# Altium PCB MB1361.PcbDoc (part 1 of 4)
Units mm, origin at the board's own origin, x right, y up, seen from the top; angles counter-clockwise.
Board outline 70 x 133.34 mm, 6 copper layers (Top Layer, Signal Layer 1, Signal Layer 2, Signal Layer 3, Signal Layer 4, Bottom Layer), stack 1.578 mm thick; 268 components, 251 nets, 1066 pads, 705 vias.
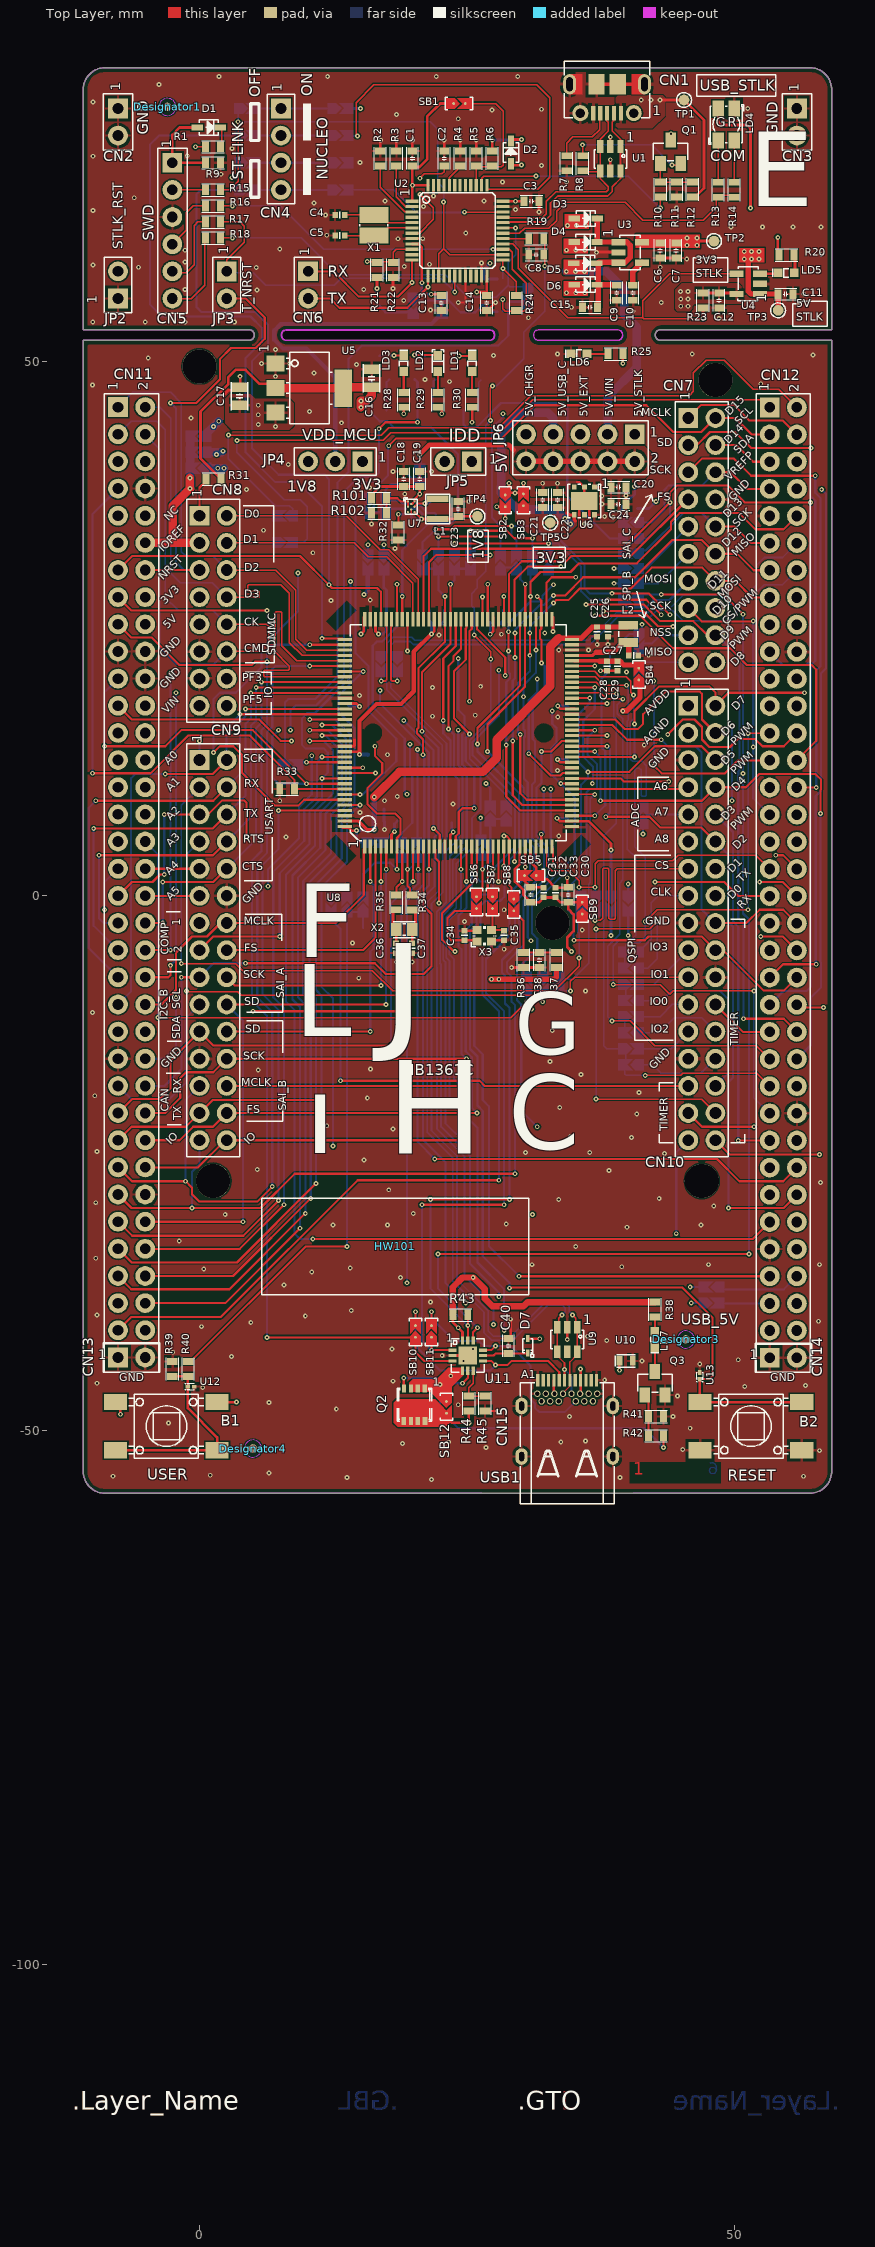
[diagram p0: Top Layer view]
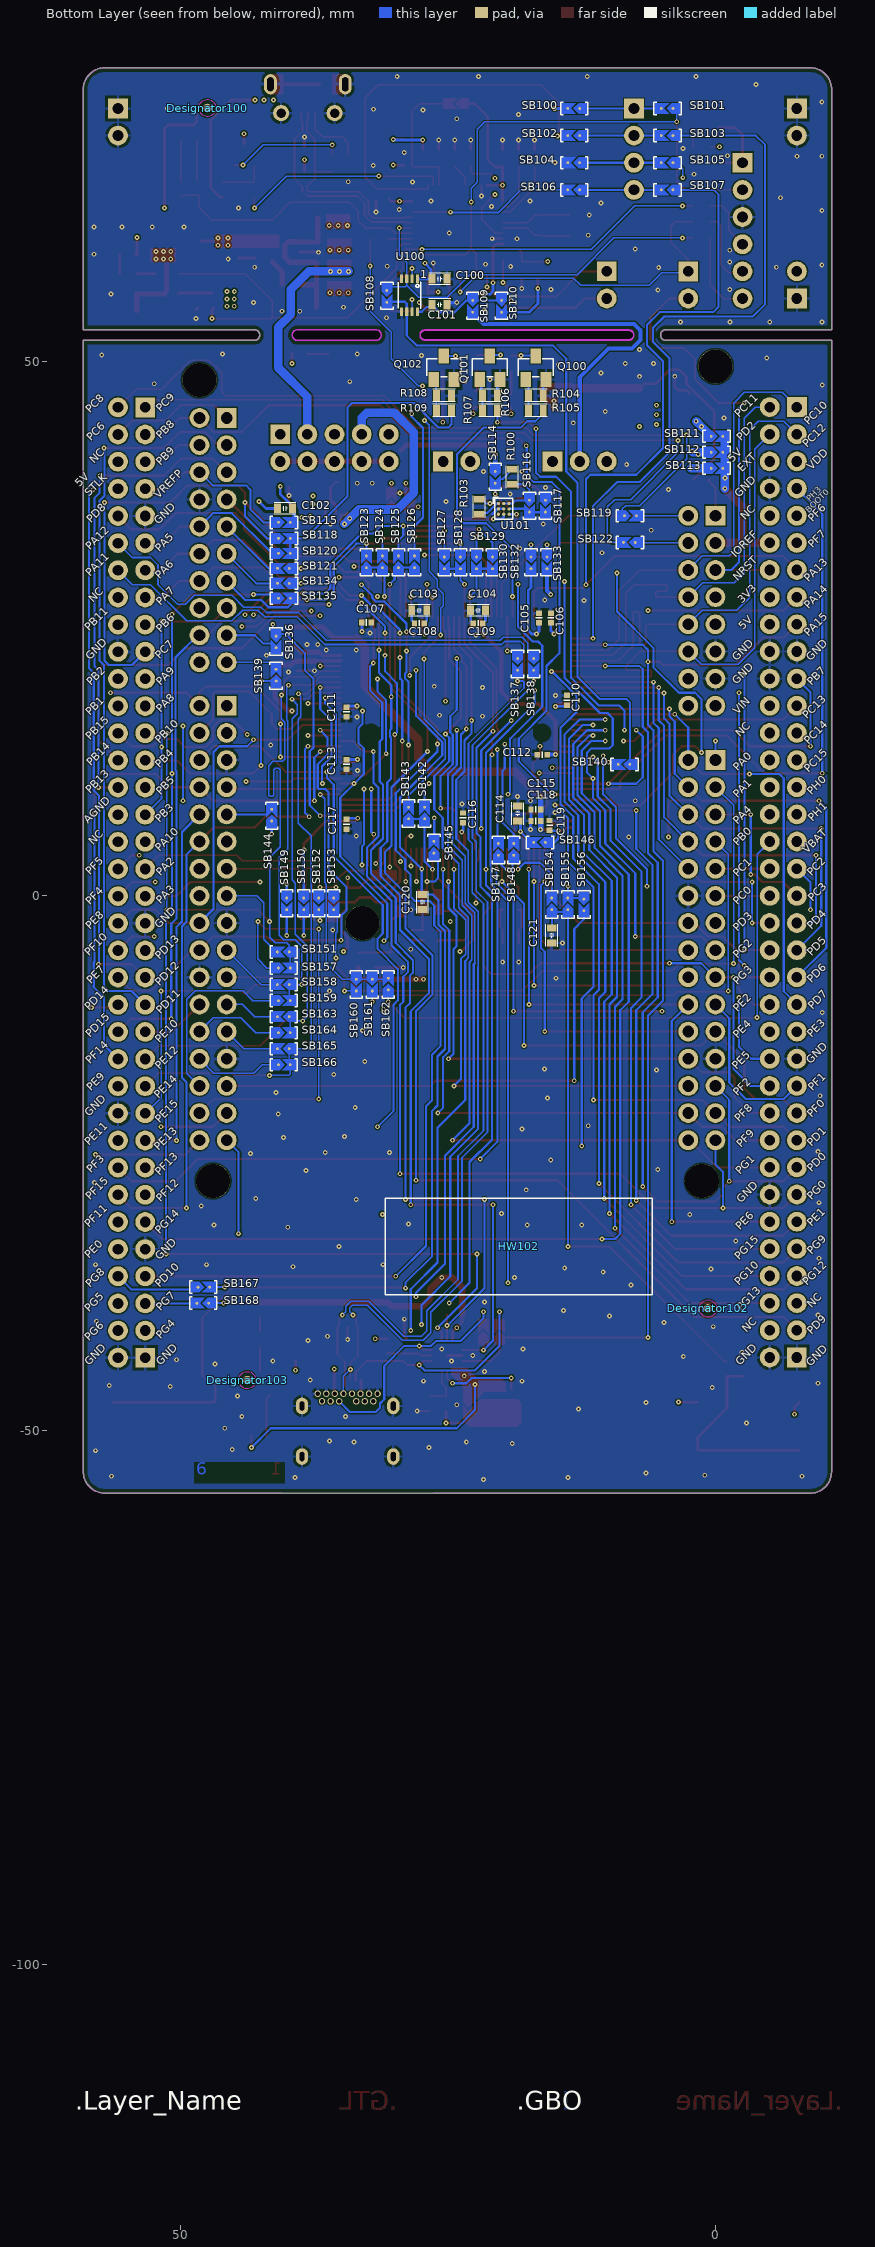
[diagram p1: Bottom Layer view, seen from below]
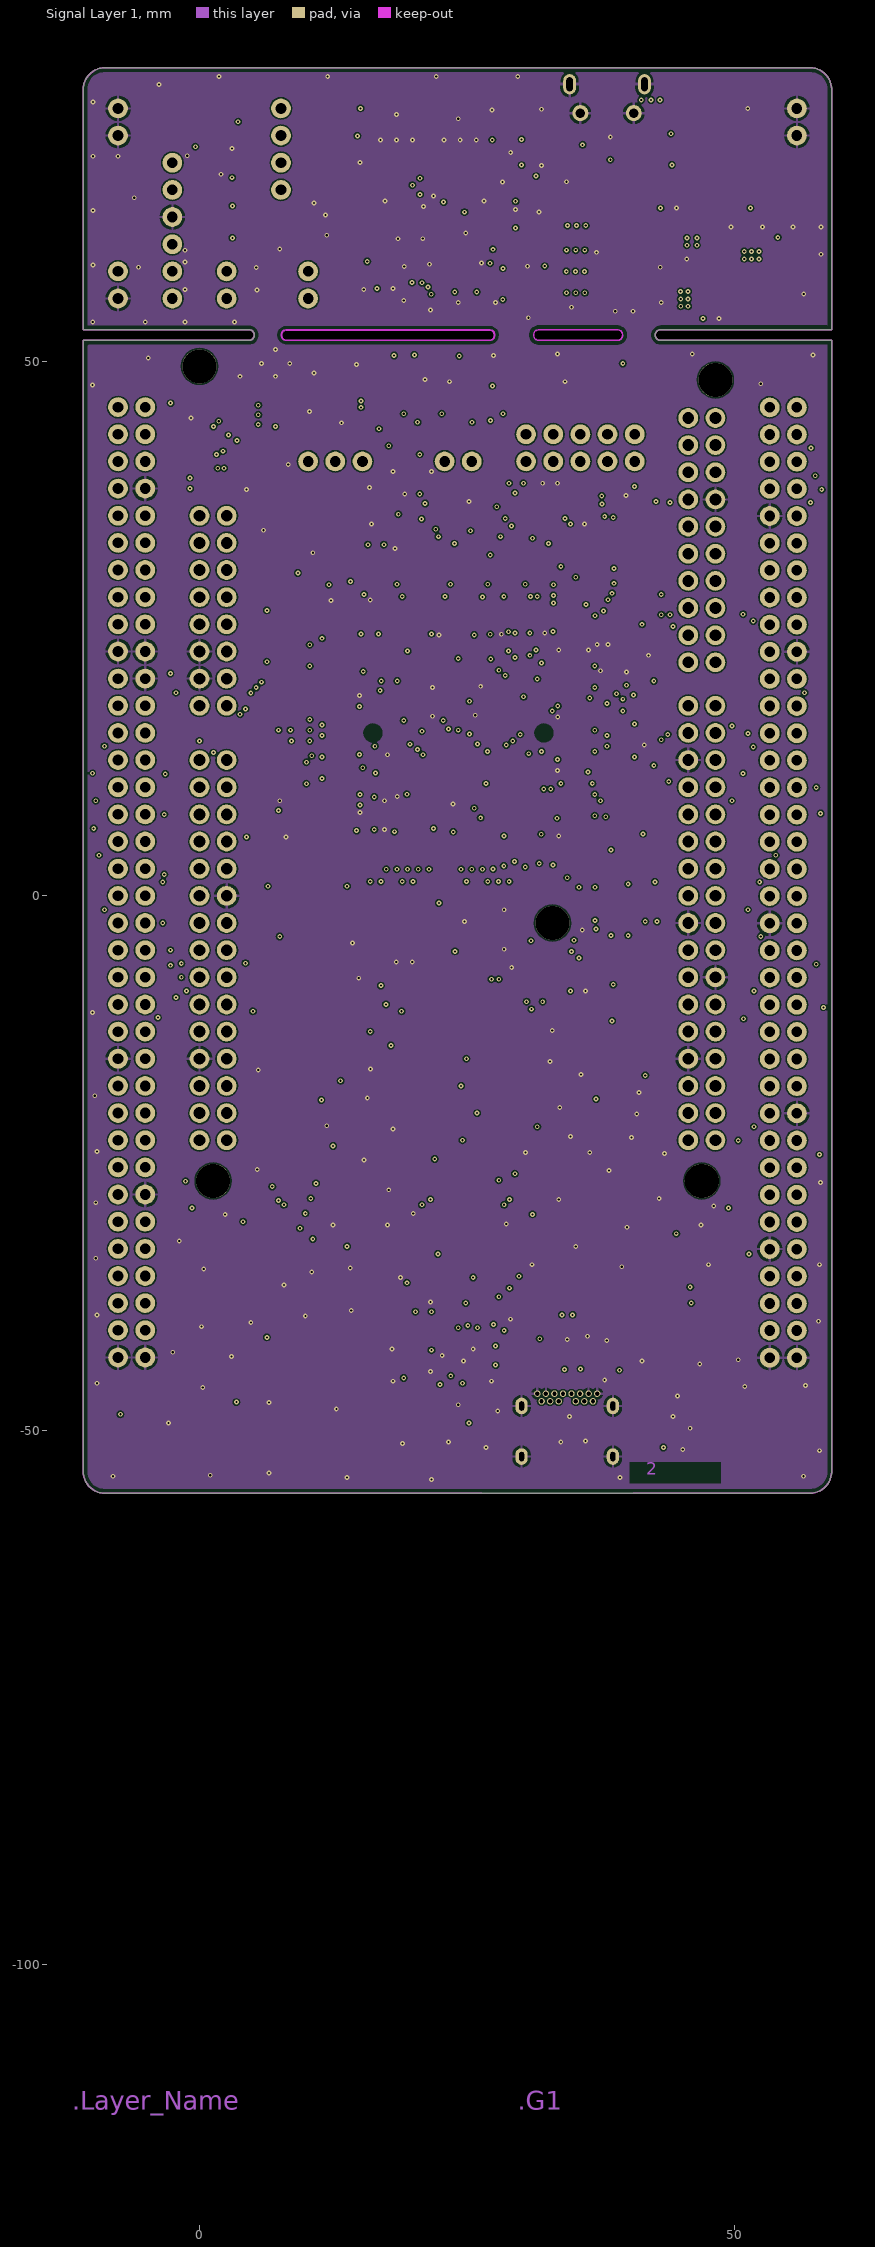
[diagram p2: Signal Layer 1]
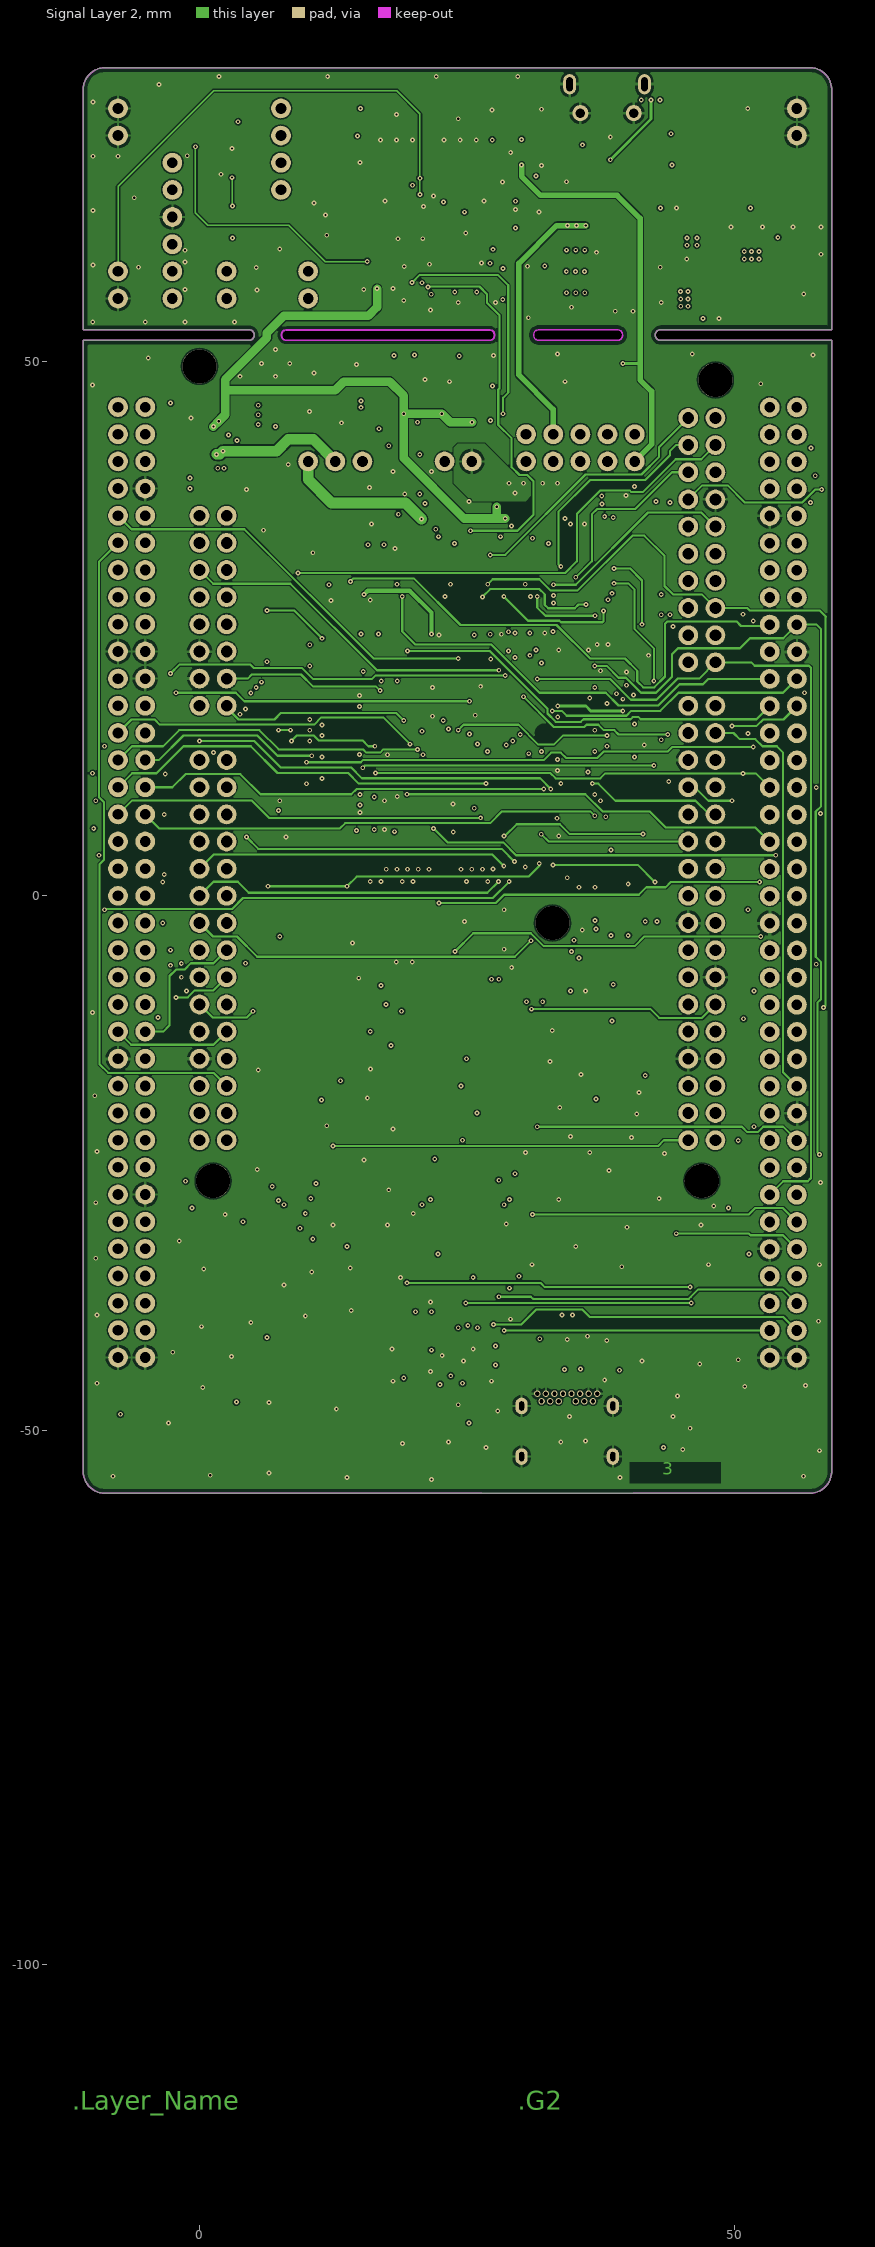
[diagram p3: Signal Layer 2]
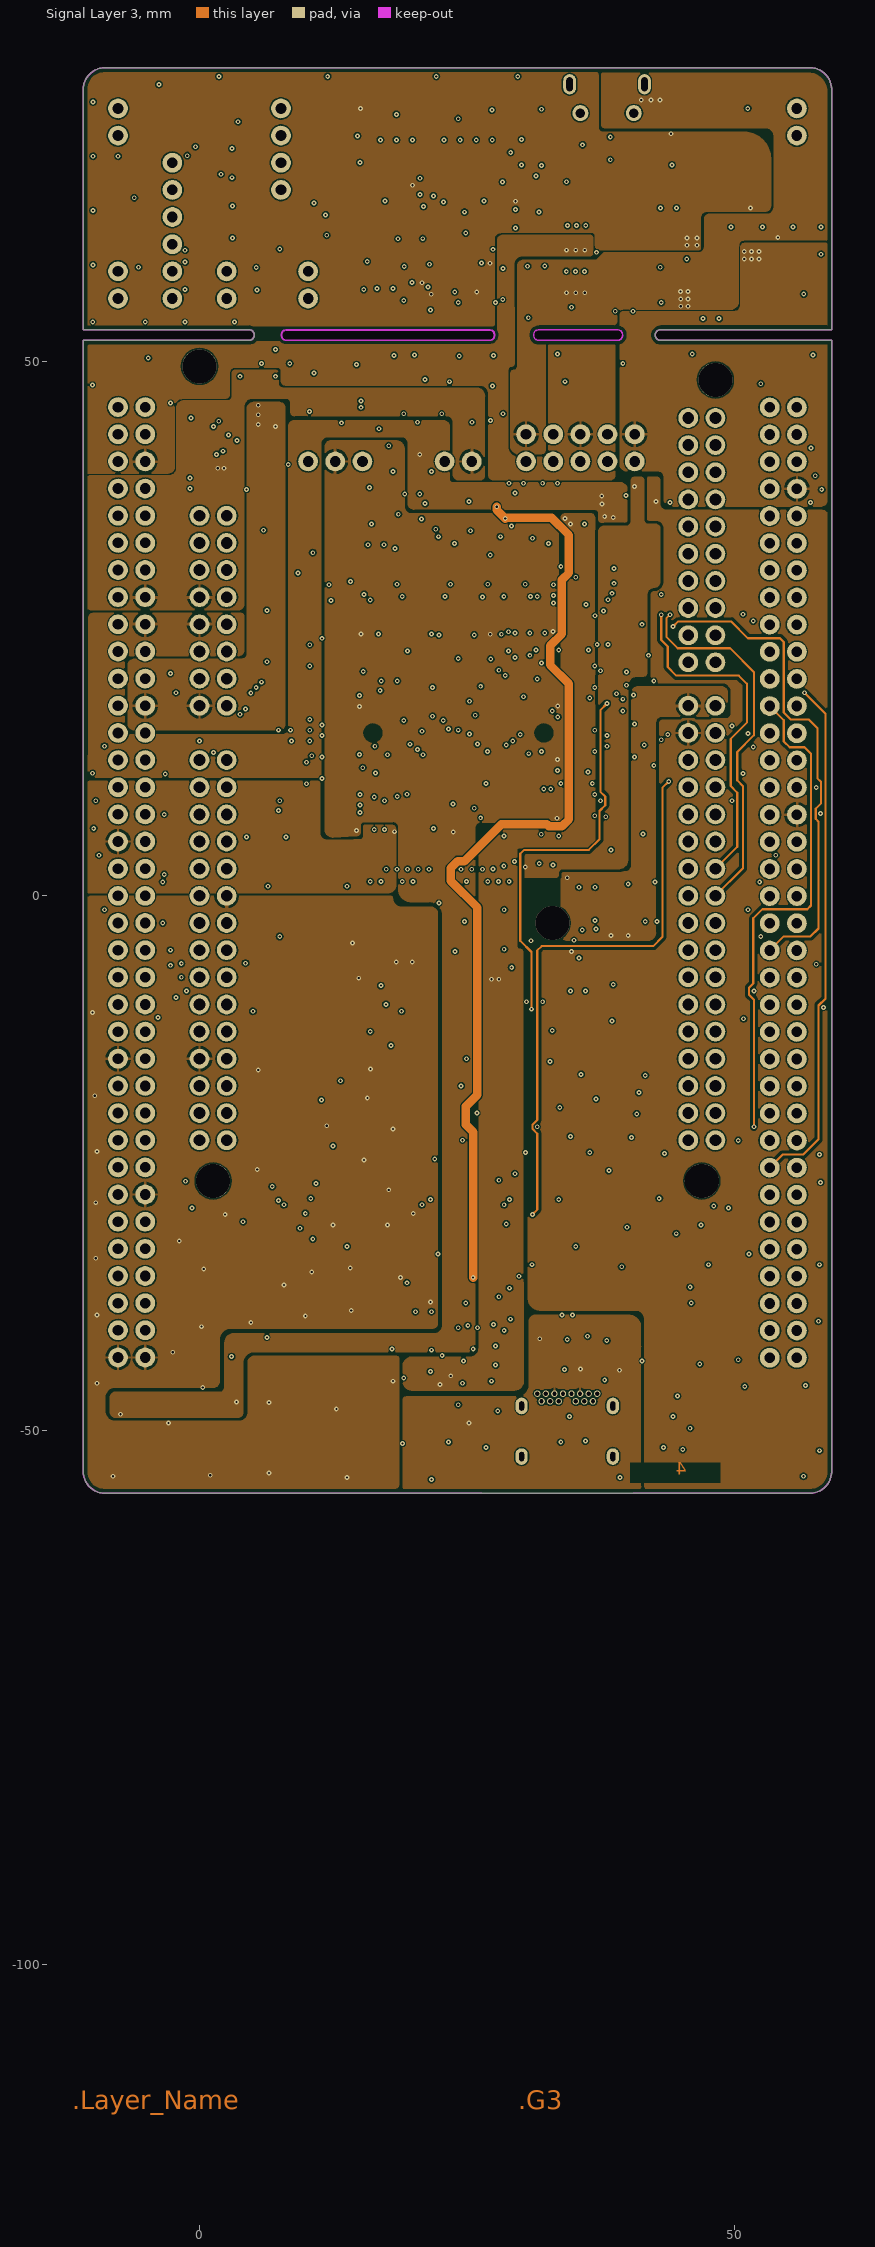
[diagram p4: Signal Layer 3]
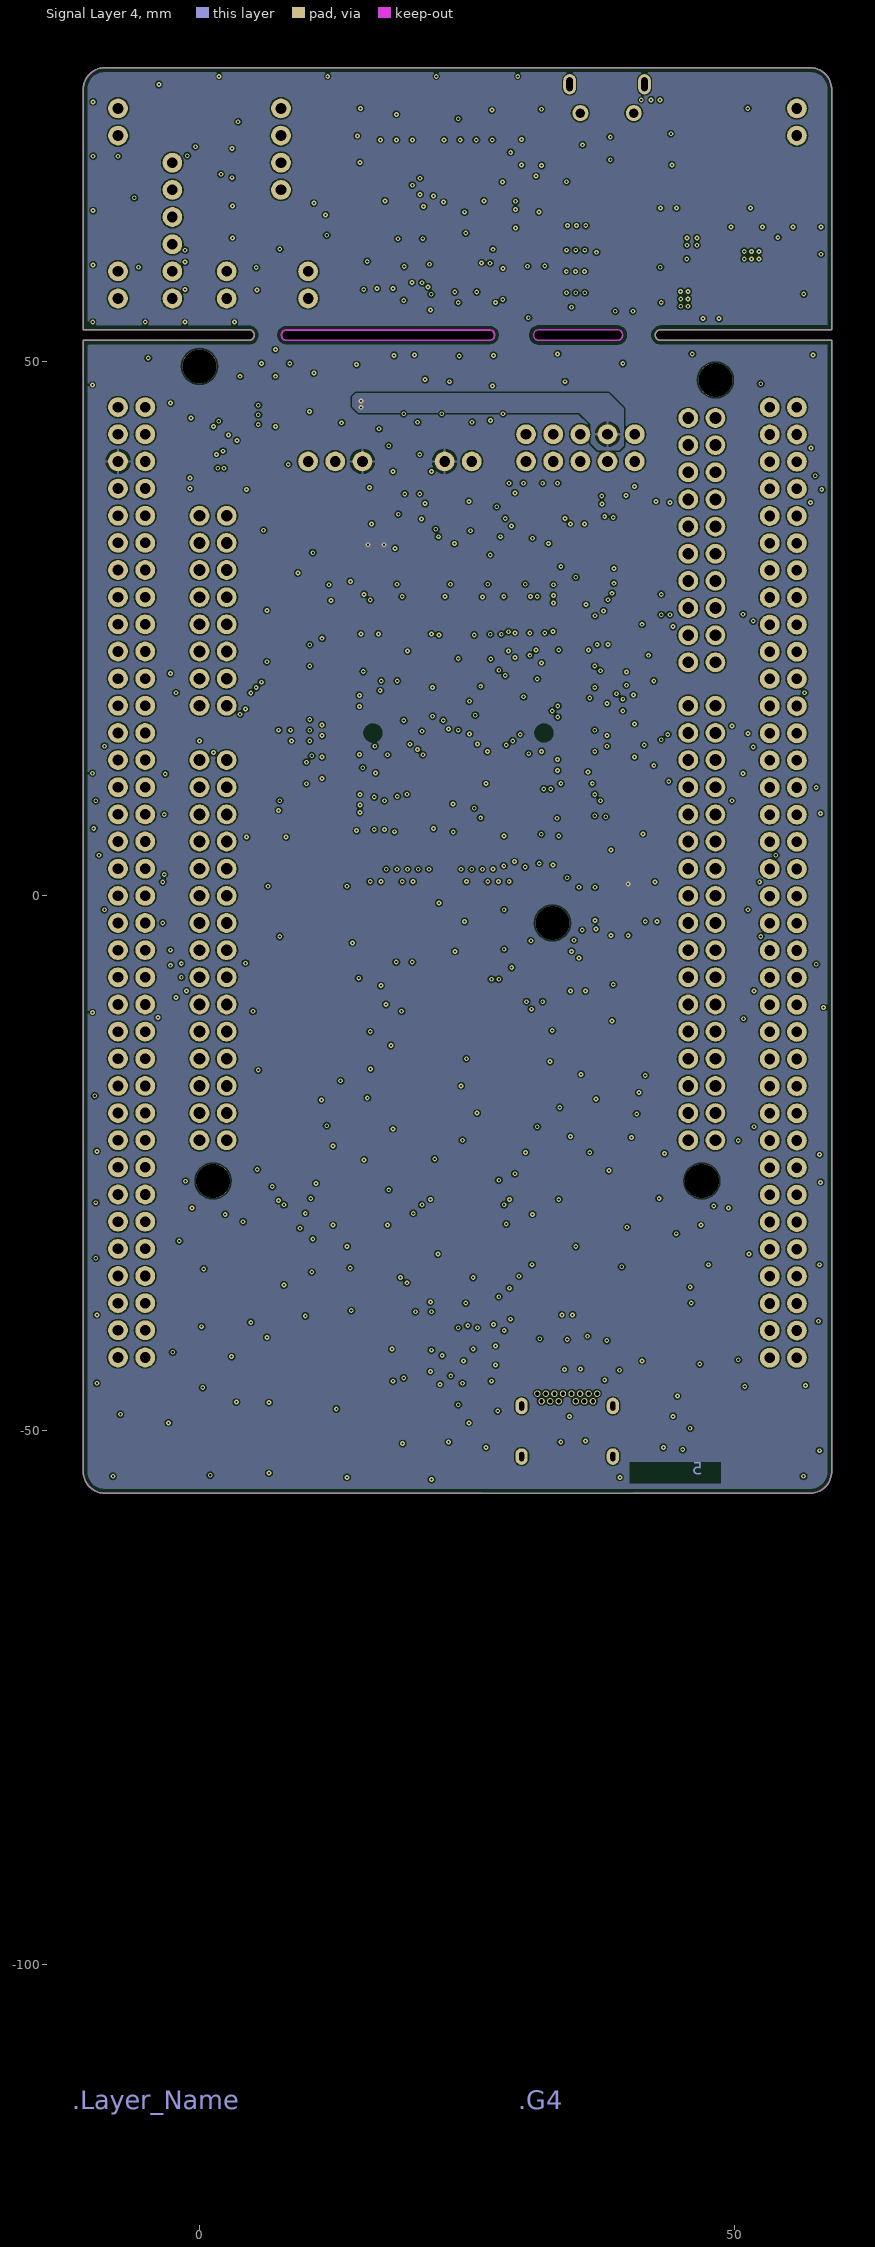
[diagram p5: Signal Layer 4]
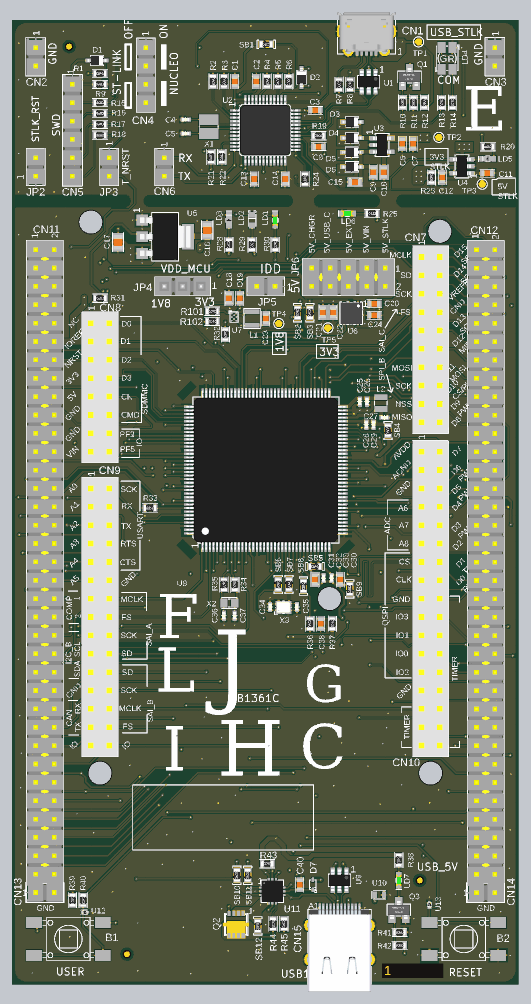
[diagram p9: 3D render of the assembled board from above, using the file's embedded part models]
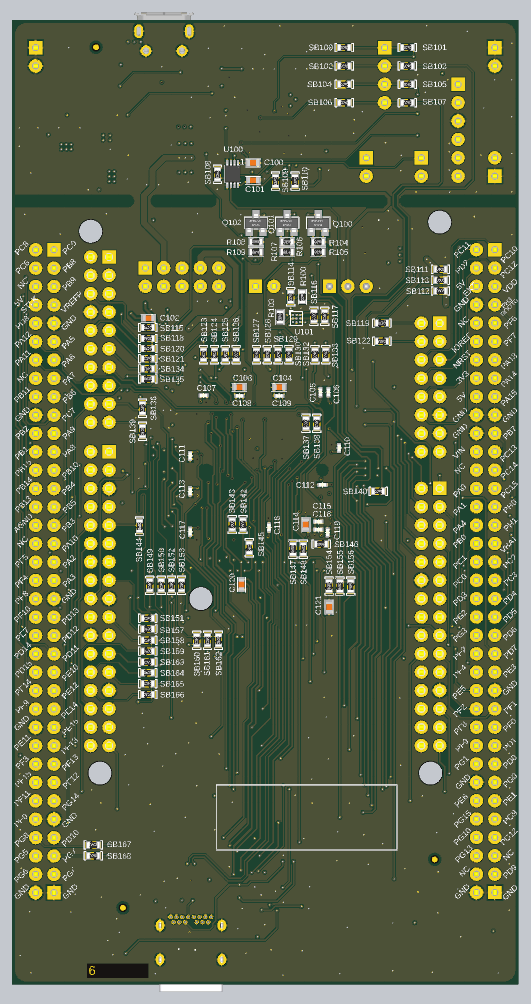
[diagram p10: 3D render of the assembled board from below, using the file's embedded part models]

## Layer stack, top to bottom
Top Solder: solder mask 0.015, Solder Resist, Dk 3.5
Top Layer: signal copper 0.042
Dielectric 1: core 0.1, FR-4, Dk 4.2
Signal Layer 1: signal copper 0.035
Dielectric 2: prepreg 0.102, Dk 4.2
Signal Layer 2: signal copper 0.035
Dielectric 3: core 0.95, Dk 4.2
Signal Layer 3: signal copper 0.035
Dielectric 4: prepreg 0.102, Dk 4.2
Signal Layer 4: signal copper 0.035
Dielectric 5: core 0.1, Dk 4.2
Bottom Layer: signal copper 0.042
Bottom Solder: solder mask 0.015, Solder Resist, Dk 3.5

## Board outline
-10.866,-53.879 ccw(c-8.866,-53.879) -8.866,-55.879 -8.87,-55.88 57.13,-55.88 57.13,-55.875 ccw(c57.13,-53.875) 59.13,-53.875 59.13,51.96 43.13,51.96 cw(c43.13,52.46) 43.13,52.96 59.13,52.96 59.13,75.46 ccw(c57.13,75.46) 57.13,77.46 -8.87,77.46 ccw(c-8.87,75.46) -10.87,75.46 -10.87,52.96 4.63,52.96 cw(c4.63,52.46) 4.63,51.96 -10.87,51.96
cut-out: 8.13,52.024 8.131,52.024 14.463,52.024 27.13,52.024 cw(c27.13,51.96) 27.131,52.024 ccw(c27.13,52.46) 27.566,52.46 ccw(c27.13,52.46) 27.13,52.896 cw(c27.13,52.96) 27.129,52.896 27.13,52.896 14.463,52.896 27.129,52.896 14.463,52.896 8.13,52.896 ccw(c8.13,52.96) 8.131,52.896 8.13,52.896 14.463,52.896 8.13,52.896 ccw(c8.13,52.46)
cut-out: 31.75,51.96 cw(c31.75,52.46) 31.75,52.96 39.08,52.96 cw(c39.08,52.46) 39.08,51.96

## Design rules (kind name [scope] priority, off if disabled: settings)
BoardOutlineClearance "BOTTOM Silksreen clearence" [OnLayer('Bottom Overlay')] p1: gap=0 ignorepadtopadclearanceinfootprint=FALSE
BoardOutlineClearance "TOP Silksreen clearence" [OnLayer('Top Overlay')] p2: gap=0 ignorepadtopadclearanceinfootprint=FALSE
BoardOutlineClearance [All] p3: gap=0.4 ignorepadtopadclearanceinfootprint=FALSE
Clearance Clearance_ALIM [InNetClass('ALIM')] p1: gap=0.127 ignorepadtopadclearanceinfootprint=FALSE except(0.15: Track-Fill SMDPad-Fill THPad-Fill Via-Fill Fill-Fill; 0.2: Arc-Track Arc-THPad Track-Track Track-THPad SMDPad-SMDPad SMDPad-THPad THPad-THPad; 0.3: Track-Poly Poly-Poly)
Clearance [All] p2: gap=0.127 ignorepadtopadclearanceinfootprint=FALSE except(0.15: Track-Fill SMDPad-Fill THPad-Fill Via-Fill Fill-Fill; 0.2: Arc-THPad Track-THPad SMDPad-SMDPad SMDPad-THPad THPad-THPad)
ComponentClearance [All] p1 off: gap=0.025 collisioncheckmode=3 verticalgap=2540 showdistances=TRUE
DiffPairsRouting [InDifferentialPairClass('USB')] p1: maxlimit=0.254 minlimit=0.226 mostfreqgap=0.254 toplayer_maxgap=0.226 toplayer_prefgap=0.226 toplayer_minwidth=0.155 toplayer_maxwidth=0.155 toplayer_prefwidth=0.155 midlayer1_mingap=0.254 midlayer1_minwidth=0.381 midlayer1_maxwidth=0.381 midlayer1_prefwidth=0.381 midlayer2_mingap=0.251 midlayer2_maxgap=0.251 midlayer2_prefgap=0.251 midlayer2_minwidth=0.13 midlayer2_maxwidth=0.13 midlayer2_prefwidth=0.13 midlayer3_mingap=0.254 midlayer3_minwidth=0.381 midlayer3_maxwidth=0.381 midlayer3_prefwidth=0.381 midlayer4_mingap=0.254 midlayer4_minwidth=0.381 midlayer4_maxwidth=0.381 midlayer4_prefwidth=0.381 bottomlayer_maxgap=0.226 bottomlayer_prefgap=0.226 bottomlayer_minwidth=0.155 bottomlayer_maxwidth=0.155 bottomlayer_prefwidth=0.155 maxuncoupledlength=12.7
Height [All] p1 off: minheight=0 maxheight=100 prefheight=0.5
HoleSize [All] p1: absolutevalues=TRUE maxlimit=10 minlimit=0.1 maxpercent=80.000 minpercent=20.000
HoleToHoleClearance [All] p1: gap=0.25 allowstackedmicrovias=TRUE
MatchedLengths MatchedLengths_JTAG [All] p1: tolerance=10 checknetsindiffpair=FALSE checkdiffpairvsdiffpair=TRUE checkxsignals=TRUE checkothers=TRUE
MatchedLengths MatchedLengths_USB [InDifferentialPairClass('USB')] p2: tolerance=2.5 checknetsindiffpair=FALSE checkdiffpairvsdiffpair=TRUE checkxsignals=TRUE checkothers=TRUE
MatchedLengths MatchedLengths_SD_CARD [All] p3: tolerance=10 checknetsindiffpair=FALSE checkdiffpairvsdiffpair=TRUE checkxsignals=TRUE checkothers=TRUE
MatchedLengths MatchedLengths_SPI [InNetClass('SPI')] p4: tolerance=7 checknetsindiffpair=FALSE checkdiffpairvsdiffpair=TRUE checkxsignals=TRUE checkothers=TRUE
MinimumSolderMaskSliver [All] p1: minsoldermaskwidth=0
PlaneClearance [All] p1: clearance=0.5
PlaneConnect [All] p1: planeconnectstyle=Relief reliefexpansion=0.5 reliefentries=4 reliefconductorwidth=0.25 reliefairgap=0.25
PolygonConnect PolygonConnect_1 [All] p1: thpad.connectstyle=Relief thpad.reliefconductorwidth=0.254 thpad.reliefentries=4 thpad.polygonreliefangle="90 Angle" thpad.airgapwidth=0.254 smdpad.connectstyle=Relief smdpad.reliefconductorwidth=0.254 smdpad.reliefentries=4 smdpad.polygonreliefangle="90 Angle" smdpad.airgapwidth=0.254 via.connectstyle=Direct via.reliefconductorwidth=0.254 via.reliefentries=4 via.polygonreliefangle="90 Angle" via.airgapwidth=0.254
RoutingVias [All] p1: holewidth=0.2 width=0.45 viastyle="Through Hole" minholewidth=0.2 minwidth=0.45 maxholewidth=0.2 maxwidth=0.45
SilkToSilkClearance [All] p1: silktosilkclearance=0
SilkToSolderMaskClearance [IsPad] p1: minsilkscreentomaskgap=0 clearancetoexposedcopper=TRUE
SolderMaskExpansion [All] p1: expansion=0.102
Width Width_50_ohms [InNetClass('50 ohms')] p1: maxlimit=0.25 minlimit=0.102 preferedwidth=0.25 toplayer_minwidth=0.127 toplayer_maxwidth=0.127 toplayer_prefwidth=0.127 midlayer1_minwidth=0.25 midlayer2_maxwidth=0.102 midlayer2_prefwidth=0.102 midlayer3_minwidth=0.25 midlayer4_minwidth=0.25 bottomlayer_minwidth=0.127 bottomlayer_maxwidth=0.127 bottomlayer_prefwidth=0.127 minimp=50.000000 maximp=50.000000 favimp=50.000000
Width Width_GND [InNetClass('GND')] p2: maxlimit=0.8 minlimit=0.19 preferedwidth=0.25 minimp=50.000000 maximp=50.000000 favimp=50.000000
Width Width_ALIM_150mA [InNetClass('ALIM_150mA')] p3: maxlimit=1 minlimit=0.25 preferedwidth=0.8 minimp=50.000000 maximp=50.000000 favimp=50.000000
Width Width_ALIM_200mA [InNetClass('ALIM_200mA')] p4: maxlimit=1 minlimit=0.25 preferedwidth=0.4 minimp=50.000000 maximp=50.000000 favimp=50.000000
Width Width_ALIM_500mA [InNetClass('ALIM_500mA')] p5: maxlimit=1 minlimit=0.25 preferedwidth=1 minimp=50.000000 maximp=50.000000 favimp=50.000000
Width Width_ALIM_1A [InNetClass('ALIM_1A')] p6: maxlimit=2 minlimit=0.25 preferedwidth=2 minimp=50.000000 maximp=50.000000 favimp=50.000000
Width Width_1 [All] p7: maxlimit=0.508 minlimit=0.127 preferedwidth=0.2 minimp=50.000000 maximp=50.000000 favimp=50.000000
20 further rules are at their usual default settings.

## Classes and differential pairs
net class GND: AGND GND
component class U_USB_Type_C: C30 CN5 HW23 HW24 JP3 LD7 Q3 R24 R29 R33 R36 R42 SB11 SB100 U7 U8
component class U_STM32_microcontroller_power: C19 C23 C24 C27 C28 C29 C30 C31 C32 C33 C35 C36 C102 C103 C104 C107 C109 C111 C113 C114 C115 C116 C117 C118 C119 L1 SB4 SB11 SB100 SB132 SB133 SB146 SB149 SB150
component class U_STM32_microcontroller_IOs: B1 B2 C30 C35 C113 C119 C120 C121 HW11 HW17 HW18 LD1 LD2 R33 R34 R35 R36 R40 R42 R109 SB7 SB10 SB100 SB123 SB124 SB125 SB126 SB127 SB128 SB129 SB130 SB137 SB138 SB140 SB142 SB143 SB145 SB147 SB148 SB154 SB155 U7 U8 X2 X3
component class U_ST_LINK_V2-1: C1 C2 C3 C4 C5 C6 C7 C8 C9 C10 C11 C12 C13 C14 C15 C36 C113 CN1 CN2 CN4 CN5 CN11 D1 D2 D3 D4 D5 D6 HW7 HW8 HW9 HW10 JP2 JP3 LD1 LD2 Q1 R1 R2 R3 R4 R5 R6 R7 R8 R9 R10 R11 R12 R13 R14 R15 R16 R17 R18 R19 R20 R21 R22 R23 R24 SB7 SB10 SB100 SB104 SB106 SB108 SB123 SB128 SB132 TP1 TP2 TP3 U1 U2 U3 U7 U100 X1
component class U_POWER_BOARD: C12 C17 C18 C19 C20 C21 C23 C24 C27 HW6 JP2 JP3 L1 LD2 R33 R109 SB3 SB114 SB116 SB117 SB124 TP1 TP2 U5 U6 U7 U100
component class U_Mechanical_Parts: HW03 HW12 HW13 HW14
component class U_ARDUINO_extension_connectors: C33 CN4 CN5 CN7 CN9 CN10 CN11 CN12 CN15 HW25 HW26 LD2 Q3 R24 R29 R109 SB111 SB112 SB113 SB115 SB118 SB119 SB120 SB121 SB122 SB134 SB135 SB136 SB139 SB144 SB151 SB152 SB153 SB156 SB157 SB158 SB159 SB160 SB161 SB162 SB163 SB164 SB165 SB166 SB167 SB168
polygon class POLY_DIRECT_ALL: NETC906_2_L01_P192
net class SPI: PA2 PB0 PB10 PE12 PE14 PE15
net class "50 ohms": MCO NetCN7_19 NetCN10_13 NetCN10_15 NetCN10_21 NetCN10_23 NetCN10_25 NetCN12_1 NetCN12_2 PA2 PB0 PB10 PC8 PC9 PC10 PC11 PC12 PD2 PE12 PE14 PE15
net class SD_CARD: PC8 PC9 PC10 PC11 PC12
differential pair class USB: STLINK_USB_D USB_FS USB_FS_SB
net class JTAG: PA13 PA14 SWO
net class ALIM_1A: 5V 5V_EXT 5V_VIN VBUSc VIN
net class ALIM_500mA: 3V3 3V3_PER 3V3_STLK 5V_STLK 5V_USB_STLK IOREF VDD VDD_MCU VDD_SMPS_1V8 VDDA
net class ALIM_200mA: VDDIO VREFP
net class ALIM_150mA: V15_COUT VDDSMPS_CIN VLX
net class ALIM: AGND VBUSc VDDA VREFP
differential pair USB_FS: +USB_FS_P -USB_FS_N
differential pair STLINK_USB_D: +STLINK_USB_D_P -STLINK_USB_D_N

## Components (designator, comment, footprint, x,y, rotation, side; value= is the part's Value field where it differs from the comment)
B1 "" SWI_WEALTHMETAL_TD-0341_4P_BLUE -3.099,-49.606 r270 top value=SW_BLUE
B2 "" SWI_WEALTHMETAL_TD-0341_4P_BLACK 51.587,-49.606 r270 top value=SW_BLACK
C1 "" C0603 19.914,68.986 r270 top value=100nF
C2 "" C0603 22.885,68.986 r270 top value=100nF
C3 "" C0603 31.05,64.975 r180 top value=100nF
C4 "" C0402 13.132,63.703 r180 top value=10pF
C5 "" C0402 13.132,61.773 r180 top value=10pF
C6 "" C0603 43.078,60.376 r90 top locked value=100nF
C7 "Capacitor" C0603 44.577,60.376 r90 top value=1uF
C8 "" C0603 31.496,59.969 r180 top value=20pF
C9 "" C0603 39.04,56.413 r90 top value=1uF
C10 "" C0603 40.538,56.413 r90 top value=10nF
C11 "" C0603 54.825,56.3 r180 top value=100nF
C12 "Capacitor" C0603 48.6,55.7 r90 top value=1uF
C13 "" C0603 22.606,55.474 r90 top value=100nF
C14 "" C0603 26.873,55.474 r90 top value=100nF
C15 "" C0603 36.525,55.067 r0 top value=100nF
C16 "" C0805 16.104,48.412 r270 top value=10uF
C17 "" C0805 3.759,46.736 r270 top value=10uF
C18 "" C0603 19.1,39 r270 top value=100nF
C19 "" C0603 20.6,39 r270 top value=10uF
C20 "Capacitor" C0603 39.2,38.24 r180 top value=1uF
C21 "" C0603 32.1,37.04 r270 top value=100nF
C22 "Capacitor" C0603 33.5,37.04 r270 top value=1uF
C23 "" C0603 24.2,36.2 r270 top value=10uF
C24 "" C0603 39.2,36.64 r180 top value=100nF
C25 "Capacitor" C0402 37.2,24.7 r90 top value=100nF
C26 "" C0402 38.2,24.7 r90 top value=4.7uF
C27 "" C0402 40.6,22.5 r180 top value=100pF
C28 "" C0402 38.1,21.5 r90 top value=10uF
C29 "" C0402 39.1,21.5 r90 top value=10uF
C30 "Capacitor" C0603 34.5,0.1 r270 top value=1uF
C31 "Capacitor" C0603 31,0.1 r270 top value=1uF
C32 "Capacitor" C0402 32.2,0.3 r90 top value=100nF
C33 "Capacitor" C0402 33.3,0.3 r90 top value=100nF
C34 "Capacitor" C0402 24.8,-3.7 r90 top value=6.8pF
C35 "Capacitor" C0402 28.5,-3.7 r270 top value=6.8pF
C36 "Capacitor" C0402 18.4,-4.9 r270 top value=3.9pF
C37 "Capacitor" C0402 19.9,-4.9 r270 top value=3.9pF
C38 "" C0603 31.8,-6 r90 top value=10pF
C40 "Capacitor" C0603 28.9,-42.1 r270 top value="100nF, 50V"
C100 "" C0603 25.806,57.709 r0 bottom value=100nF
C101 "" C0603 25.8,55.3 r180 bottom value=100nF
C102 "" C0603 40.267,36.236 r180 bottom value=100nF
C103 "" C0603 27.7,26.7 r180 bottom value=4.7uF
C104 "" C0603 22.2,26.7 r180 bottom value=4.7uF
C105 "Capacitor" C0402 16.5,26 r270 bottom value=100nF
C106 "Capacitor" C0402 15.4,26 r270 bottom value=100nF
C107 "Capacitor" C0402 32.648,25.555 r0 bottom value=100nF
C108 "Capacitor" C0402 27.7,25.5 r180 bottom value=100nF
C109 "Capacitor" C0402 22.2,25.5 r180 bottom value=100nF
C110 "Capacitor" C0402 13.9,18.3 r270 bottom value=100nF
C111 "Capacitor" C0402 34.5,17.2 r90 bottom value=100nF
C112 "Capacitor" C0402 16.2,13.2 r180 bottom value=100nF
C113 "Capacitor" C0402 34.5,12.3 r90 bottom value=100nF
C114 "Capacitor" C0603 18.5,7.7 r270 bottom value=1uF
C115 "" C0402 16.8,8.1 r180 bottom value=4.7uF
C116 "Capacitor" C0402 23.6,7.3 r270 bottom value=100nF
C117 "Capacitor" C0402 34.5,6.7 r90 bottom value=100nF
C118 "Capacitor" C0402 16.8,7 r180 bottom value=100nF
C119 "Capacitor" C0402 15.5,6.6 r270 bottom value=100nF
C120 "" C0603 27.409,-0.586 r90 bottom value=100nF
C121 "" C0603 15.3,-3.7 r90 bottom value=100nF
CN1 "" CON_USBMICROB_MOLEX_105017-0001_H2P90 38.125,77.368 r180 top value=USB_uB_105017-0001
CN2 "" CON_SAMTEC_TSW-102-09-X-S -7.62,72.39 r270 top value="Header 2x1 16mm"
CN3 "" CON_SAMTEC_TSW-102-09-X-S 55.88,72.391 r270 top value="Header 2x1 16mm"
CN4 "Header 4x1" CON_SAMTEC_TSW-104-07-G-S 7.62,69.851 r270 top
CN5 "" CON_SAMTEC_TSW-106-07-X-S -2.54,62.23 r270 top value="Header 6x1"
CN6 "" CON_SAMTEC_TSW-102-07-G-S 10.16,57.15 r270 top value="Header 2x1"
CN7 "" CON_SAMTEC_SSW-110-23-X-D_N144_ARD 46.99,33.274 r90 top value="Socket 10x2_N144_ARD"
CN8 "" CON_SAMTEC_SSW-108-23-X-D_N144_ARD 1.27,26.67 r90 top value="Socket 8x2_N144_ARD"
CN9 "" CON_SAMTEC_SSW-115-23-X-D_N144_ARD 1.27,-5.08 r90 top value="Socket 15x2_N144_ARD"
CN10 "" CON_SAMTEC_SSW-117-23-X-D_N144_ARD 46.99,-2.54 r90 top value="Socket 17x2_N144_ARD"
CN11 "" CON_SAMTEC_TSW-135-07-X-D -6.35,2.54 r270 top value="Header 35x2"
CN12 "" CON_SAMTEC_TSW-135-07-X-D 54.61,2.515 r270 top value="Header 35x2"
CN13 "" CON_SAMTEC_TSW-102-09-X-S -6.35,-43.18 r0 top value="Header 2x1 16mm"
CN14 "" CON_SAMTEC_TSW-102-09-X-S 54.61,-43.205 r0 top value="Header 2x1 16mm"
CN15 "USB_TYPE_C_Receptacle_317JD24BZTF3K3C3" CON_USB-TYPEC_COXOC_317JD24BZTF3K3C3 34.4,-55.9 r0 top value=317JD24BZTF3K3C3
D1 "" DIO_SOD323 0.864,71.882 r0 top value=BAT60JFILM
D2 "" DIO_SOD323 29.134,69.545 r90 top value=BAT60JFILM
D3 "" DIO_SOD323 36.125,63.375 r0 top value=BAT60JFILM
D4 "" DIO_SOD323 36.119,61.163 r0 top value=BAT60JFILM
D5 "" DIO_SOD323 36.093,59.182 r0 top value=BAT60JFILM
D6 "" DIO_SOD323 36.119,57.175 r0 top value=BAT60JFILM
D7 "SCHOTTKY_1A_2K" DIO_SOD523_1A_2K 30.7,-42.1 r270 top value=BAT54KFILM
Designator1 "Comment" MIRE_PLACE_SMD_0P8MM -3,73.8 r0 top
Designator3 "Comment" MIRE_PLACE_SMD_0P8MM 45.5,-41.5 r0 top
Designator4 "Comment" MIRE_PLACE_SMD_0P8MM 5,-51.7 r0 top
Designator100 "Comment" MIRE_PLACE_SMD_0P8MM 47.526,73.7 r180 bottom
Designator102 "Comment" MIRE_PLACE_SMD_0P8MM 0.7,-38.6 r180 bottom
Designator103 "Comment" MIRE_PLACE_SMD_0P8MM 43.8,-45.3 r180 bottom
HW101 "STICKER_BOARD_REF" STICKER_25X9 18.3,-32.8 r0 top value="MBxxxxy-zz syywwxxxxx"
HW102 "STICKER_BOARD_CPN" STICKER_25X9 18.4,-32.8 r180 bottom value="Board CPN"
JP2 "" CON_SAMTEC_TSW-102-07-G-S -7.62,57.15 r90 top value="Shunt not fitted"
JP3 "" CON_SAMTEC_TSW-102-07-G-S 2.54,57.149 r270 top value="Shunt Fitted"
JP4 "" CON_SAMTEC_TSW-103-07-F-S 12.7,40.64 r180 top value="Shunt Fitted 1-2"
JP5 "" CON_SAMTEC_TSW-102-07-G-S 24.2,40.64 r180 top value="Shunt Fitted"
JP6 "" CON_SAMTEC_TSW-105-07-X-D 35.63,41.91 r180 top value="Shunt Fitted 1-2"
L1 "" IND_TDK_VLS252010HBX-1 22.3,36.2 r270 top value="2.2uH 2.6A 0.100R"
L2 "Inductor" IND_TDK_MLP2016H4R7MT0S1 40.1,24.5 r270 top value=4.7uF_1.1A
LD1 "" LED_0603_GREEN 25.5,49.8 r90 top value=GREEN
LD2 "" LED_0603_VISHAY_VLMB1300-GS08_BLUE_1A2K_H0P8 22.3,49.8 r90 top value=BLUE
LD3 "" LED_0603_RED_H0P4 19.1,49.8 r90 top value=RED
LD4 "" LED_BI-GR_HSMF-A201-A00J1 49.276,72.161 r180 top value=LD_BICOLOR_CMS
LD5 "" LED_0603_RED_H0P4 54.875,58.275 r180 top value=RED
LD6 "" LED_0603_GREEN 35.5,50.7 r180 top value=GREEN
LD7 "" LED_0603_GREEN 42.6,-41.5 r270 top value=GREEN
Q1 "" NPN_SOT23 44.069,69.588 r0 top value=9013-SOT23
Q2 "STL11N3LLH6" MOS_POWERFLAT_3P3X3P3_P065 20.1,-47.6 r180 top
Q3 "" NPN_SOT23 42.6,-45.6 r0 top value=9013-SOT23
Q100 "" NPN_SOT23 16.8,49.4 r180 bottom value=9013-SOT23
Q101 "" NPN_SOT23 21.1,49.4 r180 bottom value=9013-SOT23
Q102 "" NPN_SOT23 25.4,49.4 r180 bottom value=9013-SOT23
R1 "" R0603 1.27,70.079 r180 top value=100R
R2 "" R0603 16.916,68.986 r270 top value=10K
R3 "" R0603 18.415,68.986 r270 top value=10K
R4 "" R0603 24.384,68.986 r270 top value=100K
R5 "" R0603 25.883,68.986 r90 top value=4K7
R6 "" R0603 27.381,68.986 r270 top value=2K7
R7 "" R0603 34.341,68.529 r90 top value=100K
R8 "" R0603 35.839,68.529 r270 top value=1K5
R9 "" R0603 1.27,68.58 r0 top value=10K
R10 "" R0603 43.122,66.065 r270 top value=100R
R11 "" R0603 44.62,66.065 r90 top value=36K
R12 "" R0603 46.119,66.065 r90 top value=10K
R13 "" R0603 48.525,66.05 r270 top value=330R
R14 "" R0603 50.025,66.05 r270 top value=330R
R15 "" R0603 1.27,66.04 r0 top value=22R
R16 "" R0603 1.27,64.541 r0 top value=22R
R17 "" R0603 1.27,63.043 r0 top value=22R
R18 "" R0603 1.27,61.544 r0 top value=22R
R19 "" R0603 31.496,61.468 r0 top value=100R
R20 "" R0603 54.915,59.944 r0 top value=1K
R21 "" R0603 16.612,58.539 r90 top value=4K7
R22 "" R0603 18.11,58.539 r90 top value=4K7
R23 "" R0603 47.1,55.7 r270 top value=10K
R24 "" R0603 29.616,55.474 r270 top value=100R
R25 "" R0603 38.9,50.7 r0 top value=1K
R28 "" R0603 19.1,46.4 r90 top value=1K
R29 "" R0603 22.3,46.4 r90 top value=680R
R30 "" R0603 25.5,46.4 r270 top value=510R
R31 "" R0603 1.3,39 r0 top value=1K
R32 "" R0603 18.6,34 r270 top value=19K6
R33 "" R0603 8.2,10 r180 top value=10K
R34 "" R0603 18.417,-0.604 r270 top value=0R
R35 "" R0603 19.916,-0.611 r270 top value=0R
R36 "" R0603 30.3,-6 r90 top value=49K9
R37 "" R0603 33.4,-6 r270 top value=330K
R38 "" R0603 42.6,-38.7 r270 top value=510R
R39 "" R0603 -2.54,-44.247 r270 top value=100K
R40 "" R0603 -1.05,-44.25 r270 top value=330R
R41 "" R0603 42.7,-48.7 r180 top value=22K
R42 "" R0603 42.7,-50.5 r180 top value=47K
R43 "Resistor" R0603 24.4,-39.2 r180 top value=10K
R44 "Resistor" R0603 25.2,-47.5 r270 top value=10K
R45 "Resistor" R0603 26.7,-47.5 r90 top value=2K7
R100 "" R0603 19,39.2 r270 bottom value=0R
R101 "" R0603 16.8,37.2 r180 top value=0R
R102 "" R0603 16.8,35.8 r180 top value=0R
R103 "" R0603 22.1,36.4 r270 bottom value=0R
R104 "" R0603 16.8,46.8 r0 bottom value=100K
R105 "" R0603 16.8,45.4 r0 bottom value=47K
R106 "" R0603 21.1,46.8 r0 bottom value=100K
R107 "" R0603 21.1,45.4 r0 bottom value=47K
R108 "" R0603 25.4,46.8 r0 bottom value=100K
R109 "" R0603 25.4,45.4 r0 bottom value=47K
SB1 "" SOLDER-BRIDGE_R0603-0R 24.265,74.117 r0 top
SB2 "" SOLDER-BRIDGE_R0603-0R 28.6,37 r270 top
SB3 "" SOLDER-BRIDGE_R0603-0R 30.3,37 r90 top
SB4 "" SOLDER-BRIDGE_R0603-0R 41.1,20.7 r90 top
SB5 "" SOLDER-BRIDGE_R0603-0R 31,1.9 r180 top
SB6 "" SOLDER-BRIDGE_R0603-0R 25.91,-0.585 r270 top locked
SB7 "" SOLDER-BRIDGE_R0603-0R 27.409,-0.585 r270 top locked
SB8 "" SOLDER-BRIDGE_R0603-0R 29.4,-0.8 r270 top
SB9 "" SOLDER-BRIDGE_R0603-0R 35.8,-1.2 r90 top
SB10 "" SOLDER-BRIDGE_R0603-0R 20.2,-40.8 r90 top
SB11 "" SOLDER-BRIDGE_R0603-0R 21.7,-40.8 r90 top
SB12 "" SOLDER-BRIDGE_R0603-0R 23.1,-47.8 r270 top
SB100 "" SOLDER-BRIDGE_R0603-0R 13.2,73.66 r0 bottom
SB101 "" SOLDER-BRIDGE_R0603-0R 4.47,73.66 r0 bottom
SB102 "" SOLDER-BRIDGE_R0603-0R 13.2,71.12 r0 bottom
SB103 "" SOLDER-BRIDGE_R0603-0R 4.47,71.12 r0 bottom
SB104 "" SOLDER-BRIDGE_R0603-0R 13.2,68.58 r0 bottom
SB105 "" SOLDER-BRIDGE_R0603-0R 4.47,68.58 r0 bottom
SB106 "" SOLDER-BRIDGE_R0603-0R 13.2,66.04 r0 bottom
SB107 "" SOLDER-BRIDGE_R0603-0R 4.47,66.04 r0 bottom
SB108 "" SOLDER-BRIDGE_R0603-0R 30.734,56.128 r270 bottom
SB109 "" SOLDER-BRIDGE_R0603-0R 22.7,55.2 r270 bottom
SB110 "" SOLDER-BRIDGE_R0603-0R 20,55.2 r270 bottom
SB111 "" SOLDER-BRIDGE_R0603-0R -0.1,43 r180 bottom
SB112 "" SOLDER-BRIDGE_R0603-0R -0.1,41.5 r180 bottom
SB113 "" SOLDER-BRIDGE_R0603-0R -0.1,40 r180 bottom
SB114 "" SOLDER-BRIDGE_R0603-0R 20.6,39.2 r270 bottom
SB115 "" SOLDER-BRIDGE_R0603-0R 40.367,34.936 r180 bottom
SB116 "" SOLDER-BRIDGE_R0603-0R 17.4,36.5 r270 bottom
SB117 "" SOLDER-BRIDGE_R0603-0R 15.9,36.5 r270 bottom
SB118 "" SOLDER-BRIDGE_R0603-0R 40.367,33.436 r180 bottom
SB119 "" SOLDER-BRIDGE_R0603-0R 8,35.56 r180 bottom
SB120 "" SOLDER-BRIDGE_R0603-0R 40.367,32.036 r180 bottom
SB121 "" SOLDER-BRIDGE_R0603-0R 40.367,30.636 r0 bottom
SB122 "" SOLDER-BRIDGE_R0603-0R 8,33.06 r0 bottom
SB123 "" SOLDER-BRIDGE_R0603-0R 32.65,31.2 r90 bottom
SB124 "" SOLDER-BRIDGE_R0603-0R 31.15,31.2 r90 bottom
SB125 "" SOLDER-BRIDGE_R0603-0R 29.65,31.2 r90 bottom
SB126 "" SOLDER-BRIDGE_R0603-0R 28.15,31.2 r90 bottom
SB127 "" SOLDER-BRIDGE_R0603-0R 25.35,31.2 r270 bottom
SB128 "" SOLDER-BRIDGE_R0603-0R 23.85,31.2 r270 bottom
SB129 "" SOLDER-BRIDGE_R0603-0R 22.35,31.2 r270 bottom
SB130 "" SOLDER-BRIDGE_R0603-0R 20.85,31.2 r270 bottom
SB132 "" SOLDER-BRIDGE_R0603-0R 17.25,31.2 r270 bottom
SB133 "" SOLDER-BRIDGE_R0603-0R 15.75,31.2 r270 bottom
SB134 "" SOLDER-BRIDGE_R0603-0R 40.367,29.236 r0 bottom
SB135 "" SOLDER-BRIDGE_R0603-0R 40.367,27.836 r180 bottom
SB136 "" SOLDER-BRIDGE_R0603-0R 41.1,23.8 r270 bottom
SB137 "" SOLDER-BRIDGE_R0603-0R 18.5,21.7 r270 bottom
SB138 "" SOLDER-BRIDGE_R0603-0R 17,21.7 r270 bottom
SB139 "" SOLDER-BRIDGE_R0603-0R 41.1,20.6 r90 bottom
SB140 "" SOLDER-BRIDGE_R0603-0R 8.5,12.3 r0 bottom
SB142 "" SOLDER-BRIDGE_R0603-0R 27.2,7.7 r90 bottom
SB143 "" SOLDER-BRIDGE_R0603-0R 28.7,7.7 r90 bottom
SB144 "" SOLDER-BRIDGE_R0603-0R 41.5,7.5 r90 bottom
SB145 "" SOLDER-BRIDGE_R0603-0R 26.332,4.5 r90 bottom
SB146 "" SOLDER-BRIDGE_R0603-0R 16.4,5 r0 bottom
SB147 "" SOLDER-BRIDGE_R0603-0R 20.3,4.3 r90 bottom
SB148 "" SOLDER-BRIDGE_R0603-0R 18.867,4.3 r90 bottom
SB149 "" SOLDER-BRIDGE_R0603-0R 40.1,-0.7 r270 bottom
SB150 "" SOLDER-BRIDGE_R0603-0R 38.5,-0.7 r270 bottom
SB151 "" SOLDER-BRIDGE_R0603-0R 40.375,-5.25 r0 bottom
SB152 "" SOLDER-BRIDGE_R0603-0R 37.1,-0.7 r270 bottom
SB153 "" SOLDER-BRIDGE_R0603-0R 35.7,-0.7 r270 bottom
SB154 "" SOLDER-BRIDGE_R0603-0R 15.3,-0.8 r90 bottom
SB155 "" SOLDER-BRIDGE_R0603-0R 13.8,-0.8 r90 bottom
SB156 "" SOLDER-BRIDGE_R0603-0R 12.3,-0.8 r270 bottom
SB157 "" SOLDER-BRIDGE_R0603-0R 40.375,-6.75 r180 bottom
SB158 "" SOLDER-BRIDGE_R0603-0R 40.375,-8.3 r0 bottom
SB159 "" SOLDER-BRIDGE_R0603-0R 40.375,-9.8 r180 bottom
SB160 "" SOLDER-BRIDGE_R0603-0R 33.6,-8.3 r270 bottom
SB161 "" SOLDER-BRIDGE_R0603-0R 32.1,-8.3 r270 bottom
SB162 "" SOLDER-BRIDGE_R0603-0R 30.6,-8.3 r90 bottom
SB163 "" SOLDER-BRIDGE_R0603-0R 40.375,-11.3 r0 bottom
SB164 "" SOLDER-BRIDGE_R0603-0R 40.375,-12.8 r180 bottom
SB165 "" SOLDER-BRIDGE_R0603-0R 40.375,-14.3 r0 bottom
SB166 "" SOLDER-BRIDGE_R0603-0R 40.375,-15.8 r180 bottom
SB167 "" SOLDER-BRIDGE_R0603-0R 47.9,-36.6 r180 bottom
SB168 "" SOLDER-BRIDGE_R0603-0R 47.9,-38.1 r0 bottom
TP1 "" TP_SMD_1MM 45.325,74.45 r0 top value=1mm
TP2 "" TP_SMD_1MM 48.125,61.25 r0 top value=1mm
TP3 "" TP_SMD_1MM 54.125,54.775 r0 top value=1mm
TP4 "" TP_SMD_1MM 26,35.5 r0 top value=1mm
TP5 "" TP_SMD_1MM 32.8,34.9 r0 top value=1mm
U1 "" ESD_SOT23-6L 38.43,68.943 r180 top value=USBLC6-2SC6
U2 "" ICC_LQFP48_7X7_P050 24.13,62.23 r270 top locked value=STM32F103CBT6
U3 "" REG_SOT23-5L 40.277,60.186 r270 top value=LD3985M33R
U4 "TPS2041C" MOS_SOT23-5L 51.325,57.25 r90 top
U5 "" REG_SOT223-TAB 10.287,47.498 r270 top value=LD1117S50TR
U6 "" ICC_DFN6-EPAD_3X3_P095 36,36.94 r180 top value=LD39050PU33R
U7 "" ICC_FLIP-CHIP-BGA8_1P11X1P41_P040 19.812,36.4 r0 top value=ST1PS01EJR
U8 "STM32L552ZET6QU" ICC_LQFP144_20X20_P050 24.217,15.24 r90 top
U9 "USBLC6-2SC6" ESD_SOT23-6L 34.4,-41.5 r180 top
U10 "ESD-TRANSIL" ESD_QFN1610_2N_1K_2A 39.9,-43.5 r0 top value=ESDA25P35-1U1M
U11 "TCPP01-M12" ICC_QFN12L-EPAD_3X3_P050 25.1,-43 r270 top
U12 "" ESD_ST0201 -0.8,-45.9 r0 top value=ESDALC6V1-1U2
U13 "" ESD_ST0201 46.8,-44.9 r90 top value=ESDALC6V1-1U2
U100 "" ICC_VSSOP8_DCU_R-PDSO-G8_2X2P30_P050 28.626,56.185 r0 bottom value=SN74LVC2T45DCUT
U101 "" ICC_WLCSP9_1P65X1P87_P050 19.8,36.2 r180 bottom value=ADP5301ACBZ-2-R7
X1 "" CRY_NX3225GD_2P 16.307,62.738 r270 top value=NX3225GD-8.00M
X2 "XTAL_2_PINS" CRY_NX2012SA_2P 19.154,-3.151 r180 top value="NX2012SA 32.768KHz"
X3 "XTAL_4_PINS" CRY_NX2016SA_4P 26.647,-3.735 r0 top value="NX2016SA 16MHz"

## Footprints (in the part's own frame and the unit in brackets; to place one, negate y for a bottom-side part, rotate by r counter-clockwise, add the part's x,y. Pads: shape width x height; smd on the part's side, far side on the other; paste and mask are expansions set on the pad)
C0402 [mm]
  rect 0.51x0.56 smd mask+0.05: 1(-0.45,0) 2(0.45,0)
  silkscreen extent 0,-0.3 0,0.3, body extent -0.5,-0.3 0.5,0.3, height 0.4
C0603 [mm]
  rect 0.64x0.89 smd mask+0.05: 1(-0.7,0) 2(0.7,0)
  silkscreen extent -1.05,-0.55 1.02,0.55, body extent -0.9,-0.5 0.9,0.5, height 1.4
C0805 [mm]
  rect 0.9x1.4 smd mask+0.05: 1(-0.85,0) 2(0.85,0)
  silkscreen extent -1.3,-0.77 1.3,0.77, body extent -1.1,-0.7 1.1,0.7, height 1.35
CON_SAMTEC_SSW-108-23-X-D_N144_ARD [mm] "NUCLEO144_ARDUINO CONNECTOR"
  rect 1.85x1.85 / inner round 1.85 / far side rect 1.85x1.85 hole 1.1 mask+0.05: 1(8.89,1.27)
  round 1.85 hole 1.1 mask+0.05: 2(8.89,-1.27) 3(6.35,1.27) 4(6.35,-1.27) 5(3.81,1.27) 6(3.81,-1.27) 7(1.27,1.27) 8(1.27,-1.27) 9(-1.27,1.27) 10(-1.27,-1.27) 11(-3.81,1.27) 12(-3.81,-1.27) 13(-6.35,1.27) 14(-6.35,-1.27) 15(-8.89,1.27) 16(-8.89,-1.27)
  silkscreen extent -10.42,-2.47 10.42,2.47, body extent -10.42,-2.48 10.42,2.48, height 8.51
CON_SAMTEC_SSW-110-23-X-D_N144_ARD [mm] "NUCLEO144_ARDUINO CONNECTOR"
  rect 1.85x1.85 / inner round 1.85 / far side rect 1.85x1.85 hole 1.1 mask+0.05: 1(11.43,1.27)
  round 1.85 hole 1.1 mask+0.05: 2(11.43,-1.27) 3(8.89,1.27) 4(8.89,-1.27) 5(6.35,1.27) 6(6.35,-1.27) 7(3.81,1.27) 8(3.81,-1.27) 9(1.27,1.27) 10(1.27,-1.27) 11(-1.27,1.27) 12(-1.27,-1.27) 13(-3.81,1.27) 14(-3.81,-1.27) 15(-6.35,1.27) 16(-6.35,-1.27) 17(-8.89,1.27) 18(-8.89,-1.27) 19(-11.43,1.27) 20(-11.43,-1.27)
  silkscreen extent -12.96,-2.47 12.96,2.47, body extent -12.96,-2.48 12.96,2.48, height 8.51
CON_SAMTEC_SSW-115-23-X-D_N144_ARD [mm] "NUCLEO144_ARDUINO CONNECTOR"
  rect 1.85x1.85 / inner round 1.85 / far side rect 1.85x1.85 hole 1.1 mask+0.05: 1(17.78,1.27)
  round 1.85 hole 1.1 mask+0.05: 2(17.78,-1.27) 3(15.24,1.27) 4(15.24,-1.27) 5(12.7,1.27) 6(12.7,-1.27) 7(10.16,1.27) 8(10.16,-1.27) 9(7.62,1.27) 10(7.62,-1.27) 11(5.08,1.27) 12(5.08,-1.27) 13(2.54,1.27) 14(2.54,-1.27) 15(0,1.27) 16(0,-1.27) 17(-2.54,1.27) 18(-2.54,-1.27) 19(-5.08,1.27) 20(-5.08,-1.27) 21(-7.62,1.27) 22(-7.62,-1.27) 23(-10.16,1.27) 24(-10.16,-1.27) 25(-12.7,1.27) 26(-12.7,-1.27) 27(-15.24,1.27) 28(-15.24,-1.27) 29(-17.78,1.27) 30(-17.78,-1.27)
  silkscreen extent -19.31,-2.47 19.31,2.47, body extent -19.31,-2.48 19.31,2.48, height 8.51
CON_SAMTEC_SSW-117-23-X-D_N144_ARD [mm] "NUCLEO144_ARDUINO CONNECTOR"
  rect 1.85x1.85 / inner round 1.85 / far side rect 1.85x1.85 hole 1.1 mask+0.05: 1(20.32,1.27)
  round 1.85 hole 1.1 mask+0.05: 2(20.32,-1.27) 3(17.78,1.27) 4(17.78,-1.27) 5(15.24,1.27) 6(15.24,-1.27) 7(12.7,1.27) 8(12.7,-1.27) 9(10.16,1.27) 10(10.16,-1.27) 11(7.62,1.27) 12(7.62,-1.27) 13(5.08,1.27) 14(5.08,-1.27) 15(2.54,1.27) 16(2.54,-1.27) 17(0,1.27) 18(0,-1.27) 19(-2.54,1.27) 20(-2.54,-1.27) 21(-5.08,1.27) 22(-5.08,-1.27) 23(-7.62,1.27) 24(-7.62,-1.27) 25(-10.16,1.27) 26(-10.16,-1.27) 27(-12.7,1.27) 28(-12.7,-1.27) 29(-15.24,1.27) 30(-15.24,-1.27) 31(-17.78,1.27) 32(-17.78,-1.27) 33(-20.32,1.27) 34(-20.32,-1.27)
  silkscreen extent -21.85,-2.47 21.85,2.47, body extent -21.85,-2.48 21.85,2.48, height 8.51
CON_SAMTEC_TSW-102-07-G-S [mm]
  rect 1.85x1.85 / inner round 1.85 / far side rect 1.85x1.85 hole 1 mask+0.05: 1(-1.27,0)
  round 1.85 hole 1 mask+0.05: 2(1.27,0)
  silkscreen extent -2.58,-1.3 2.58,1.3, body extent -2.67,-1.3 2.58,1.3, height 8.38
CON_SAMTEC_TSW-102-09-X-S [mm]
  rect 1.85x1.85 / inner round 1.85 / far side rect 1.85x1.85 hole 1 mask+0.05: 1(-1.27,0)
  round 1.85 hole 1 mask+0.05: 2(1.27,0)
  silkscreen extent -2.64,-1.37 2.64,1.37, body extent -2.67,-1.3 2.58,1.3, height 8.38
CON_SAMTEC_TSW-103-07-F-S [mm]
  rect 1.85x1.85 / inner round 1.85 / far side rect 1.85x1.85 hole 1 mask+0.05: 1(-2.54,0)
  round 1.85 hole 1 mask+0.05: 2(0,0) 3(2.54,0)
  silkscreen extent -3.85,-1.3 3.85,1.3, body extent -3.91,-1.37 3.91,1.37, height 8.38
CON_SAMTEC_TSW-104-07-G-S [mm]
  rect 1.85x1.85 / inner round 1.85 / far side rect 1.85x1.85 hole 1 mask+0.05: 1(-3.81,0)
  round 1.85 hole 1 mask+0.05: 2(-1.27,0) 3(1.27,0) 4(3.81,0)
  silkscreen extent -5.12,-1.3 5.12,1.3, body extent -5.21,-1.37 5.18,1.37, height 8.38
CON_SAMTEC_TSW-105-07-X-D [mm]
  rect 1.85x1.85 / inner round 1.85 / far side rect 1.85x1.85 hole 1 mask+0.05: 1(-5.08,-1.27)
  round 1.85 hole 1 mask+0.05: 2(-5.08,1.27) 3(-2.54,-1.27) 4(-2.54,1.27) 5(0,-1.27) 6(0,1.27) 7(2.54,-1.27) 8(2.54,1.27) 9(5.08,-1.27) 10(5.08,1.27)
  silkscreen extent -6.35,-2.54 6.35,2.54, body extent -6.35,-2.54 6.35,2.55, height 8.38
CON_SAMTEC_TSW-106-07-X-S [mm]
  rect 1.85x1.85 / inner round 1.85 / far side rect 1.85x1.85 hole 1 mask+0.05: 1(-6.35,0)
  round 1.85 hole 1 mask+0.05: 2(-3.81,0) 3(-1.27,0) 4(1.27,0) 5(3.81,0) 6(6.35,0)
  silkscreen extent -7.73,-1.37 7.72,1.37, body extent -7.75,-1.37 7.72,1.37, height 8.38
CON_SAMTEC_TSW-135-07-X-D [mm]
  rect 1.85x1.85 / inner round 1.85 / far side rect 1.85x1.85 hole 1 mask+0.05: 1(-43.18,-1.27)
  round 1.85 hole 1 mask+0.05: 2(-43.18,1.27) 3(-40.64,-1.27) 4(-40.64,1.27) 5(-38.1,-1.27) 6(-38.1,1.27) 7(-35.56,-1.27) 8(-35.56,1.27) 9(-33.02,-1.27) 10(-33.02,1.27) 11(-30.48,-1.27) 12(-30.48,1.27) 13(-27.94,-1.27) 14(-27.94,1.27) 15(-25.4,-1.27) 16(-25.4,1.27) 17(-22.86,-1.27) 18(-22.86,1.27) 19(-20.32,-1.27) 20(-20.32,1.27) 21(-17.78,-1.27) 22(-17.78,1.27) 23(-15.24,-1.27) 24(-15.24,1.27) 25(-12.7,-1.27) 26(-12.7,1.27) 27(-10.16,-1.27) 28(-10.16,1.27) 29(-7.62,-1.27) 30(-7.62,1.27) 31(-5.08,-1.27) 32(-5.08,1.27) 33(-2.54,-1.27) 34(-2.54,1.27) 35(0,-1.27) 36(0,1.27) 37(2.54,-1.27) 38(2.54,1.27) 39(5.08,-1.27) 40(5.08,1.27) 41(7.62,-1.27) 42(7.62,1.27) 43(10.16,-1.27) 44(10.16,1.27) 45(12.7,-1.27) 46(12.7,1.27) 47(15.24,-1.27) 48(15.24,1.27) 49(17.78,-1.27) 50(17.78,1.27) 51(20.32,-1.27) 52(20.32,1.27) 53(22.86,-1.27) 54(22.86,1.27) 55(25.4,-1.27) 56(25.4,1.27) 57(27.94,-1.27) 58(27.94,1.27) 59(30.48,-1.27) 60(30.48,1.27) 61(33.02,-1.27) 62(33.02,1.27) 63(35.56,-1.27) 64(35.56,1.27) 65(38.1,-1.27) 66(38.1,1.27) 67(40.64,-1.27) 68(40.64,1.27) 69(43.18,-1.27) 70(43.18,1.27)
  silkscreen extent -44.45,-2.54 44.45,2.54, body extent -44.45,-2.54 44.45,2.54, height 8.38
CON_USB-TYPEC_COXOC_317JD24BZTF3K3C3 [mm]
  rect 0.3x1.2 smd mask+0.05: A1(-2.75,10.58) A2(-2.25,10.58) A3(-1.75,10.58) A4(-1.25,10.58) A5(-0.75,10.58) A6(-0.25,10.58) A7(0.25,10.58) A8(0.75,10.58) A9(1.25,10.58) A10(1.75,10.58) A11(2.25,10.58) A12(2.75,10.58)
  round 0.6 hole 0.4 mask+0.05: B1(2,9.33) B1(2.8,9.33) B2(2.4,8.62) B3(1.6,8.62) B4(1.2,9.33) B5(0.8,8.62) B6(0.4,9.33) B7(-0.4,9.33) B8(-0.8,8.62) B9(-1.2,9.33) B10(-1.6,8.62) B11(-2.4,8.62) B12(-2.8,9.33) B12(-2,9.33)
  oval 1.15x1.55 hole 0.45 slot 0.85 at 90 deg mask+0.05: SH1(-4.27,8.18) SH2(-4.27,3.45) SH3(4.27,8.18) SH4(4.27,3.45)
  silkscreen extent -4.38,-0.95 4.38,10.38, body extent -4.38,-0.95 4.38,10.84, height 3.03
CON_USBMICROB_MOLEX_105017-0001_H2P90 [mm]
  rect 0.4x1.35 smd mask+0.05: 1(-1.3,4.15) 2(-0.65,4.15) 3(0,4.15) 4(0.65,4.15) 5(1.3,4.15)
  round 1.5 hole 0.9 mask+0.05: 6(-2.5,4.15) 7(2.5,4.15)
  oval 1.2x1.9 hole 0.6 slot 1.3 at 90 deg mask+0.05: 8(3.5,1.45) 9(-3.5,1.45)
  rect 1.5x1.9 smd mask+0.05: 10(-1,1.45) 11(1,1.45)
  Top Layer region: 2.3,2.4 3.5,2.4 3.5,0.5 2.3,0.5 2.3,2.4
  Top Layer region: -3.5,2.4 -2.3,2.4 -2.3,0.5 -3.5,0.5 -3.5,2.4
  silkscreen extent -4,-0.7 4,4.6, body extent -4.1,-1.15 4.1,4.66, height 2.9
CRY_NX2012SA_2P [mm]
  rect 1x1.25 smd mask+0.05: 1(-0.75,0) 2(0.75,0)
  silkscreen extent -1.05,-0.75 1.05,0.75, body extent -1.05,-0.63 1.05,0.63, height 0.6
CRY_NX2016SA_4P [mm]
  rect 0.85x0.75 smd mask+0.05: 1(-0.675,-0.525) 2(0.675,-0.525) 3(0.675,0.525) 4(-0.675,0.525)
  silkscreen extent -1.22,-1.02 1.05,0.85, body extent -1.05,-0.85 1.05,0.85, height 0.7
CRY_NX3225GD_2P [mm]
  rect 1.5x2.7 smd mask+0.05: 1(-0.95,0) 2(0.95,0)
  silkscreen extent -0.1,-1.3 0.1,1.3, body extent -1.65,-1.3 1.65,1.3, height 1
DIO_SOD323 [mm]
  rect 1.06x0.54 smd mask+0.05: 1(-1.07,0) 2(1.07,0)
  silkscreen extent -0.9,-0.72 0.9,0.72, body extent -1.3,-0.78 1.3,0.78, height 1.17
DIO_SOD523_1A_2K [mm] "MCD-01677"
  rect 0.65x0.3 smd mask+0.05: 1(-0.675,0) 2(0.675,0)
  silkscreen extent -0.65,-0.45 1.05,0.55, body extent -0.85,-0.45 0.85,0.45, height 0.71
ESD_QFN1610_2N_1K_2A [mm] "DFN, 2-Leads, Body 1.60x1.00mm"
  rect 0.55x0.9 smd mask+0.05: 1(-0.625,0) 2(0.625,0)
  silkscreen extent -1.02,-0.58 0.85,0.58, body extent -0.85,-0.55 0.85,0.55, height 0.6
ESD_SOT23-6L [mm]
  rect 0.6x1.2 smd mask+0.05: 1(-0.95,-1.15) 2(0,-1.15) 3(0.95,-1.15) 4(0.95,1.15) 5(0,1.15) 6(-0.95,1.15)
  silkscreen extent -1.53,-0.87 1.53,0.87, body extent -1.52,-1.5 1.52,1.5, height 1.45
ESD_ST0201 [mm]
  rect 0.425x0.33 smd mask+0.05: 1(-0.312,0) 2(0.312,0)
  silkscreen extent -0.55,-0.3 0.33,0.3, body extent -0.34,-0.18 0.34,0.18, height 0.34
ICC_DFN6-EPAD_3X3_P095 [mm]
  rect 0.45x0.5 smd mask+0.05: 1(-0.95,-1.3) 2(0,-1.3) 3(0.95,-1.3) 4(0.95,1.3) 5(0,1.3) 6(-0.95,1.3)
  rect 2.5x1.7 smd mask+0.05: EP(0,0)
  silkscreen extent -1.55,-1.55 1.55,1.55, body extent -1.55,-1.55 1.55,1.55, height 1
ICC_FLIP-CHIP-BGA8_1P11X1P41_P040 [mm] "MCD-00228"
  round 0.2 smd paste+0.025 mask+0.05: A1(-0.312,0.5) A3(0.312,0.5) B2(0,0.25) C1(-0.312,0) C3(0.312,0) D2(0,-0.25) E1(-0.312,-0.5) E3(0.312,-0.5)
  silkscreen extent -0.7,-0.72 0.57,0.85, body extent -0.57,-0.72 0.57,0.72, height 0.61
ICC_LQFP48_7X7_P050 [mm]
  rect 0.3x1.2 smd mask+0.05: 1(-2.75,-4.25) 2(-2.25,-4.25) 3(-1.75,-4.25) 4(-1.25,-4.25) 5(-0.75,-4.25) 6(-0.25,-4.25) 7(0.25,-4.25) 8(0.75,-4.25) 9(1.25,-4.25) 10(1.75,-4.25) 11(2.25,-4.25) 12(2.75,-4.25) 25(2.75,4.25) 26(2.25,4.25) 27(1.75,4.25) 28(1.25,4.25) 29(0.75,4.25) 30(0.25,4.25) 31(-0.25,4.25) 32(-0.75,4.25) 33(-1.25,4.25) 34(-1.75,4.25) 35(-2.25,4.25) 36(-2.75,4.25)
  rect 1.2x0.3 smd mask+0.05: 13(4.25,-2.75) 14(4.25,-2.25) 15(4.25,-1.75) 16(4.25,-1.25) 17(4.25,-0.75) 18(4.25,-0.25) 19(4.25,0.25) 20(4.25,0.75) 21(4.25,1.25) 22(4.25,1.75) 23(4.25,2.25) 24(4.25,2.75) 37(-4.25,2.75) 38(-4.25,2.25) 39(-4.25,1.75) 40(-4.25,1.25) 41(-4.25,0.75) 42(-4.25,0.25) 43(-4.25,-0.25) 44(-4.25,-0.75) 45(-4.25,-1.25) 46(-4.25,-1.75) 47(-4.25,-2.25) 48(-4.25,-2.75)
  silkscreen extent -3.52,-3.52 3.52,3.52, body extent -4.5,-4.5 4.5,4.5, height 1.6
ICC_LQFP144_20X20_P050 [mm]
  rect 1.35x0.3 smd mask+0.05: 1(-10.625,8.75) 2(-10.625,8.25) 3(-10.625,7.75) 4(-10.625,7.25) 5(-10.625,6.75) 6(-10.625,6.25) 7(-10.625,5.75) 8(-10.625,5.25) 9(-10.625,4.75) 10(-10.625,4.25) 11(-10.625,3.75) 12(-10.625,3.25) 13(-10.625,2.75) 14(-10.625,2.25) 15(-10.625,1.75) 16(-10.625,1.25) 17(-10.625,0.75) 18(-10.625,0.25) 19(-10.625,-0.25) 20(-10.625,-0.75) 21(-10.625,-1.25) 22(-10.625,-1.75) 23(-10.625,-2.25) 24(-10.625,-2.75) 25(-10.625,-3.25) 26(-10.625,-3.75) 27(-10.625,-4.25) 28(-10.625,-4.75) 29(-10.625,-5.25) 30(-10.625,-5.75) 31(-10.625,-6.25) 32(-10.625,-6.75) 33(-10.625,-7.25) 34(-10.625,-7.75) 35(-10.625,-8.25) 36(-10.625,-8.75) 73(10.625,-8.75) 74(10.625,-8.25) 75(10.625,-7.75) 76(10.625,-7.25) 77(10.625,-6.75) 78(10.625,-6.25) 79(10.625,-5.75) 80(10.625,-5.25) 81(10.625,-4.75) 82(10.625,-4.25) 83(10.625,-3.75) 84(10.625,-3.25) 85(10.625,-2.75) 86(10.625,-2.25) 87(10.625,-1.75) 88(10.625,-1.25) 89(10.625,-0.75) 90(10.625,-0.25) 91(10.625,0.25) 92(10.625,0.75) 93(10.625,1.25) 94(10.625,1.75) 95(10.625,2.25) 96(10.625,2.75) 97(10.625,3.25) 98(10.625,3.75) 99(10.625,4.25) 100(10.625,4.75) 101(10.625,5.25) 102(10.625,5.75) 103(10.625,6.25) 104(10.625,6.75) 105(10.625,7.25) 106(10.625,7.75) 107(10.625,8.25) 108(10.625,8.75)
  rect 0.3x1.35 smd mask+0.05: 37(-8.75,-10.625) 38(-8.25,-10.625) 39(-7.75,-10.625) 40(-7.25,-10.625) 41(-6.75,-10.625) 42(-6.25,-10.625) 43(-5.75,-10.625) 44(-5.25,-10.625) 45(-4.75,-10.625) 46(-4.25,-10.625) 47(-3.75,-10.625) 48(-3.25,-10.625) 49(-2.75,-10.625) 50(-2.25,-10.625) 51(-1.75,-10.625) 52(-1.25,-10.625) 53(-0.75,-10.625) 54(-0.25,-10.625) 55(0.25,-10.625) 56(0.75,-10.625) 57(1.25,-10.625) 58(1.75,-10.625) 59(2.25,-10.625) 60(2.75,-10.625) 61(3.25,-10.625) 62(3.75,-10.625) 63(4.25,-10.625) 64(4.75,-10.625) 65(5.25,-10.625) 66(5.75,-10.625) 67(6.25,-10.625) 68(6.75,-10.625) 69(7.25,-10.625) 70(7.75,-10.625) 71(8.25,-10.625) 72(8.75,-10.625) 109(8.75,10.625) 110(8.25,10.625) 111(7.75,10.625) 112(7.25,10.625) 113(6.75,10.625) 114(6.25,10.625) 115(5.75,10.625) 116(5.25,10.625) 117(4.75,10.625) 118(4.25,10.625) 119(3.75,10.625) 120(3.25,10.625) 121(2.75,10.625) 122(2.25,10.625) 123(1.75,10.625) 124(1.25,10.625) 125(0.75,10.625) 126(0.25,10.625) 127(-0.25,10.625) 128(-0.75,10.625) 129(-1.25,10.625) 130(-1.75,10.625) 131(-2.25,10.625) 132(-2.75,10.625) 133(-3.25,10.625) 134(-3.75,10.625) 135(-4.25,10.625) 136(-4.75,10.625) 137(-5.25,10.625) 138(-5.75,10.625) 139(-6.25,10.625) 140(-6.75,10.625) 141(-7.25,10.625) 142(-7.75,10.625) 143(-8.25,10.625) 144(-8.75,10.625)
  silkscreen extent -10.1,-10.1 10.1,10.1, body extent -11,-11 11,11, height 1.6
ICC_QFN12L-EPAD_3X3_P050 [mm] "MCD-01809"
  rect 0.3x0.75 smd mask+0.05: 1(-0.5,-1.425) 2(0,-1.425) 3(0.5,-1.425) 7(0.5,1.425) 8(0,1.425) 9(-0.5,1.425)
  rect 0.75x0.3 smd mask+0.05: 4(1.425,-0.5) 5(1.425,0) 6(1.425,0.5) 10(-1.425,0.5) 11(-1.425,0) 12(-1.425,-0.5)
  rect 1.7x1.7 smd mask+0.05: 13(0,0)
  silkscreen extent -1.55,-1.55 1.55,1.55, body extent -1.55,-1.55 1.55,1.55, height 0.8
ICC_VSSOP8_DCU_R-PDSO-G8_2X2P30_P050 [mm]
  rect 0.3x0.8 smd mask+0.05: 1(-0.75,-1.55) 2(-0.25,-1.55) 3(0.25,-1.55) 4(0.75,-1.55) 5(0.75,1.55) 6(0.25,1.55) 7(-0.25,1.55) 8(-0.75,1.55)
  silkscreen extent -1.05,-1.2 1.05,1.2, body extent -1.05,-1.62 1.05,1.62, height 0.9
ICC_WLCSP9_1P65X1P87_P050 [mm]
  round 0.3 smd mask+0.05: A1(-0.5,0.5) A2(0,0.5) A3(0.5,0.5) B1(-0.5,0) B2(0,0) B3(0.5,0) C1(-0.5,-0.5) C2(0,-0.5) C3(0.5,-0.5)
  silkscreen extent -0.97,-0.97 0.85,1.1, body extent -0.85,-0.97 0.85,0.97, height 0.67
IND_TDK_MLP2016H4R7MT0S1 [mm] "MCD-01786"
  rect 0.8x1.8 smd mask+0.05: 1(-0.8,0) 2(0.8,0)
  silkscreen extent -0.28,-0.87 0.28,0.87, body extent -1.07,-0.87 1.08,0.87, height 1
IND_TDK_VLS252010HBX-1 [mm]
  rect 0.6x2 smd mask+0.05: 1(-0.95,0) 2(0.95,0)
  silkscreen extent -1.38,-1.12 1.38,1.12, body extent -1.35,-1.1 1.35,1.1, height 1.01
LED_0603_GREEN [mm]
  rect 0.8x0.8 smd mask+0.05: 1(-0.75,0) 2(0.75,0)
  silkscreen extent -0.25,-0.4 1.25,0.4, body extent -0.8,-0.4 0.8,0.4, height 0.6
LED_0603_RED_H0P4 [mm]
  rect 0.8x0.8 smd mask+0.05: 1(-0.75,0) 2(0.75,0)
  silkscreen extent -0.25,-0.4 1.25,0.4, body extent -0.8,-0.4 0.79,0.4, height 0.4
LED_0603_VISHAY_VLMB1300-GS08_BLUE_1A2K_H0P8 [mm]
  rect 0.8x0.8 smd mask+0.05: 1(-0.75,0) 2(0.75,0)
  silkscreen extent -0.85,-0.53 1.28,0.53, body extent -0.85,-0.45 0.85,0.45, height 0.8
LED_BI-GR_HSMF-A201-A00J1 [mm]
  rect 1.1x1.5 smd mask+0.05: 1(-0.75,-1.5) 2(-0.75,1.5) 3(0.75,1.5) 4(0.75,-1.5)
  silkscreen extent -1.65,-1.85 1.65,1.85, body extent -1.5,-1.85 1.5,1.85, height 2.1
MIRE_PLACE_SMD_0P8MM [mm]
  round 0.8 smd paste-10 mask+0.2: 1(0,0)
  Top Layer keep-out circle w0.01: c0,0 r0.804
MOS_POWERFLAT_3P3X3P3_P065 [mm] "MCD-01126"
  rect 0.4x0.75 smd mask+0.05: 1(-0.975,-1.525) 2(-0.325,-1.525) 3(0.325,-1.525) 4(0.975,-1.525) 6(0.325,1.525) 7(-0.325,1.525)
  rect 0.45x0.75 smd mask+0.05: 5(1,1.525) 8(-1,1.525)
  Top Layer region: -1.755,0.2 -1.755,-0.2 -1.225,-0.2 -1.225,-0.5 1.225,-0.5 1.225,-0.2 1.755,-0.2 1.755,0.2 1.225,0.2 1.225,1.9 -1.225,1.9 -1.225,0.2
  silkscreen extent -1.63,-1.55 1.63,1.55, body extent -1.75,-1.75 1.75,1.75, height 0.91
MOS_SOT23-5L [mm]
  rect 0.6x1.3 smd mask+0.05: 1(-0.95,-1.1) 2(0,-1.1) 3(0.95,-1.1) 4(0.95,1.1) 5(-0.95,1.1)
  silkscreen extent -1.6,-0.95 1.6,0.97, body extent -1.52,-1.25 1.52,1.25, height 1.45
NPN_SOT23 [mm]
  rect 1x1.4 smd mask+0.05: 1(-0.95,-1.1) 2(0.95,-1.1) 3(0,1.1)
  silkscreen extent -1.63,-0.82 1.63,0.82, body extent -1.56,-1.25 1.56,1.25, height 1.1
R0603 [mm]
  rect 0.64x1 smd mask+0.05: 1(-0.7,0) 2(0.7,0)
  silkscreen extent -1.05,-0.58 1.05,0.58, body extent -0.9,-0.5 0.9,0.5, height 0.56
REG_SOT23-5L [mm]
  rect 0.6x1.3 smd mask+0.05: 1(-0.95,-1.1) 2(0,-1.1) 3(0.95,-1.1) 4(0.95,1.1) 5(-0.95,1.1)
  silkscreen extent -1.6,-0.95 1.6,0.97, body extent -1.52,-1.25 1.52,1.25, height 1.1
REG_SOT223-TAB [mm]
  rect 1.5x1.65 smd mask+0.05: 1(-2.3,-3.175) 2(0,-3.175) 3(2.3,-3.175)
  rect 3.5x1.65 smd mask+0.05: 4(0,3.175)
  silkscreen extent -3.35,-2.15 3.35,2.12, body extent -3.35,-3.48 3.35,3.48, height 1.8
SOLDER-BRIDGE_R0603-0R [mil]
  round 10 smd paste-393.7: 1(-19.69,0) 2(23.62,0)
  Top Layer region: -47.24,-19.68 -47.24,19.68 -15.75,19.68 3.94,0 -15.75,-19.68 -47.24,-19.68
  Top Layer region: -5.91,19.68 13.78,0 -5.91,-19.68 47.24,-19.68 47.24,19.68 -5.91,19.68
  silkscreen extent -50,-23 50,23, body extent -36,-20 36,20, height 22
STICKER_25X9 [mm] "Sticker 25mm x 9mm"
  silkscreen extent -12.5,-4.5 12.5,4.5
SWI_WEALTHMETAL_TD-0341_4P_BLACK [mm]
  rect 1.52x2.16 smd mask+0.05: 1(-2.25,-4.75) 2(-2.25,4.75) 3(2.25,-4.75) 4(2.25,4.75)
  silkscreen extent -3,-3.5 3,3.5, body extent -3,-5.15 3,5.15, height 7.55
SWI_WEALTHMETAL_TD-0341_4P_BLUE [mm]
  rect 1.52x2.16 smd mask+0.05: 1(-2.25,-4.75) 2(-2.25,4.75) 3(2.25,-4.75) 4(2.25,4.75)
  silkscreen extent -3,-3.5 3,3.5, body extent -3,-5.15 3,5.15, height 7.55
TP_SMD_1MM [mm]
  round 1 smd paste-10 mask+0.05: 1(0,0)
  silkscreen extent -0.7,-0.7 0.7,0.7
